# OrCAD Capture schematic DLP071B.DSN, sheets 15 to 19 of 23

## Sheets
15 PAGE09 - 2ND PMD POWER SUPPLIES: size A3
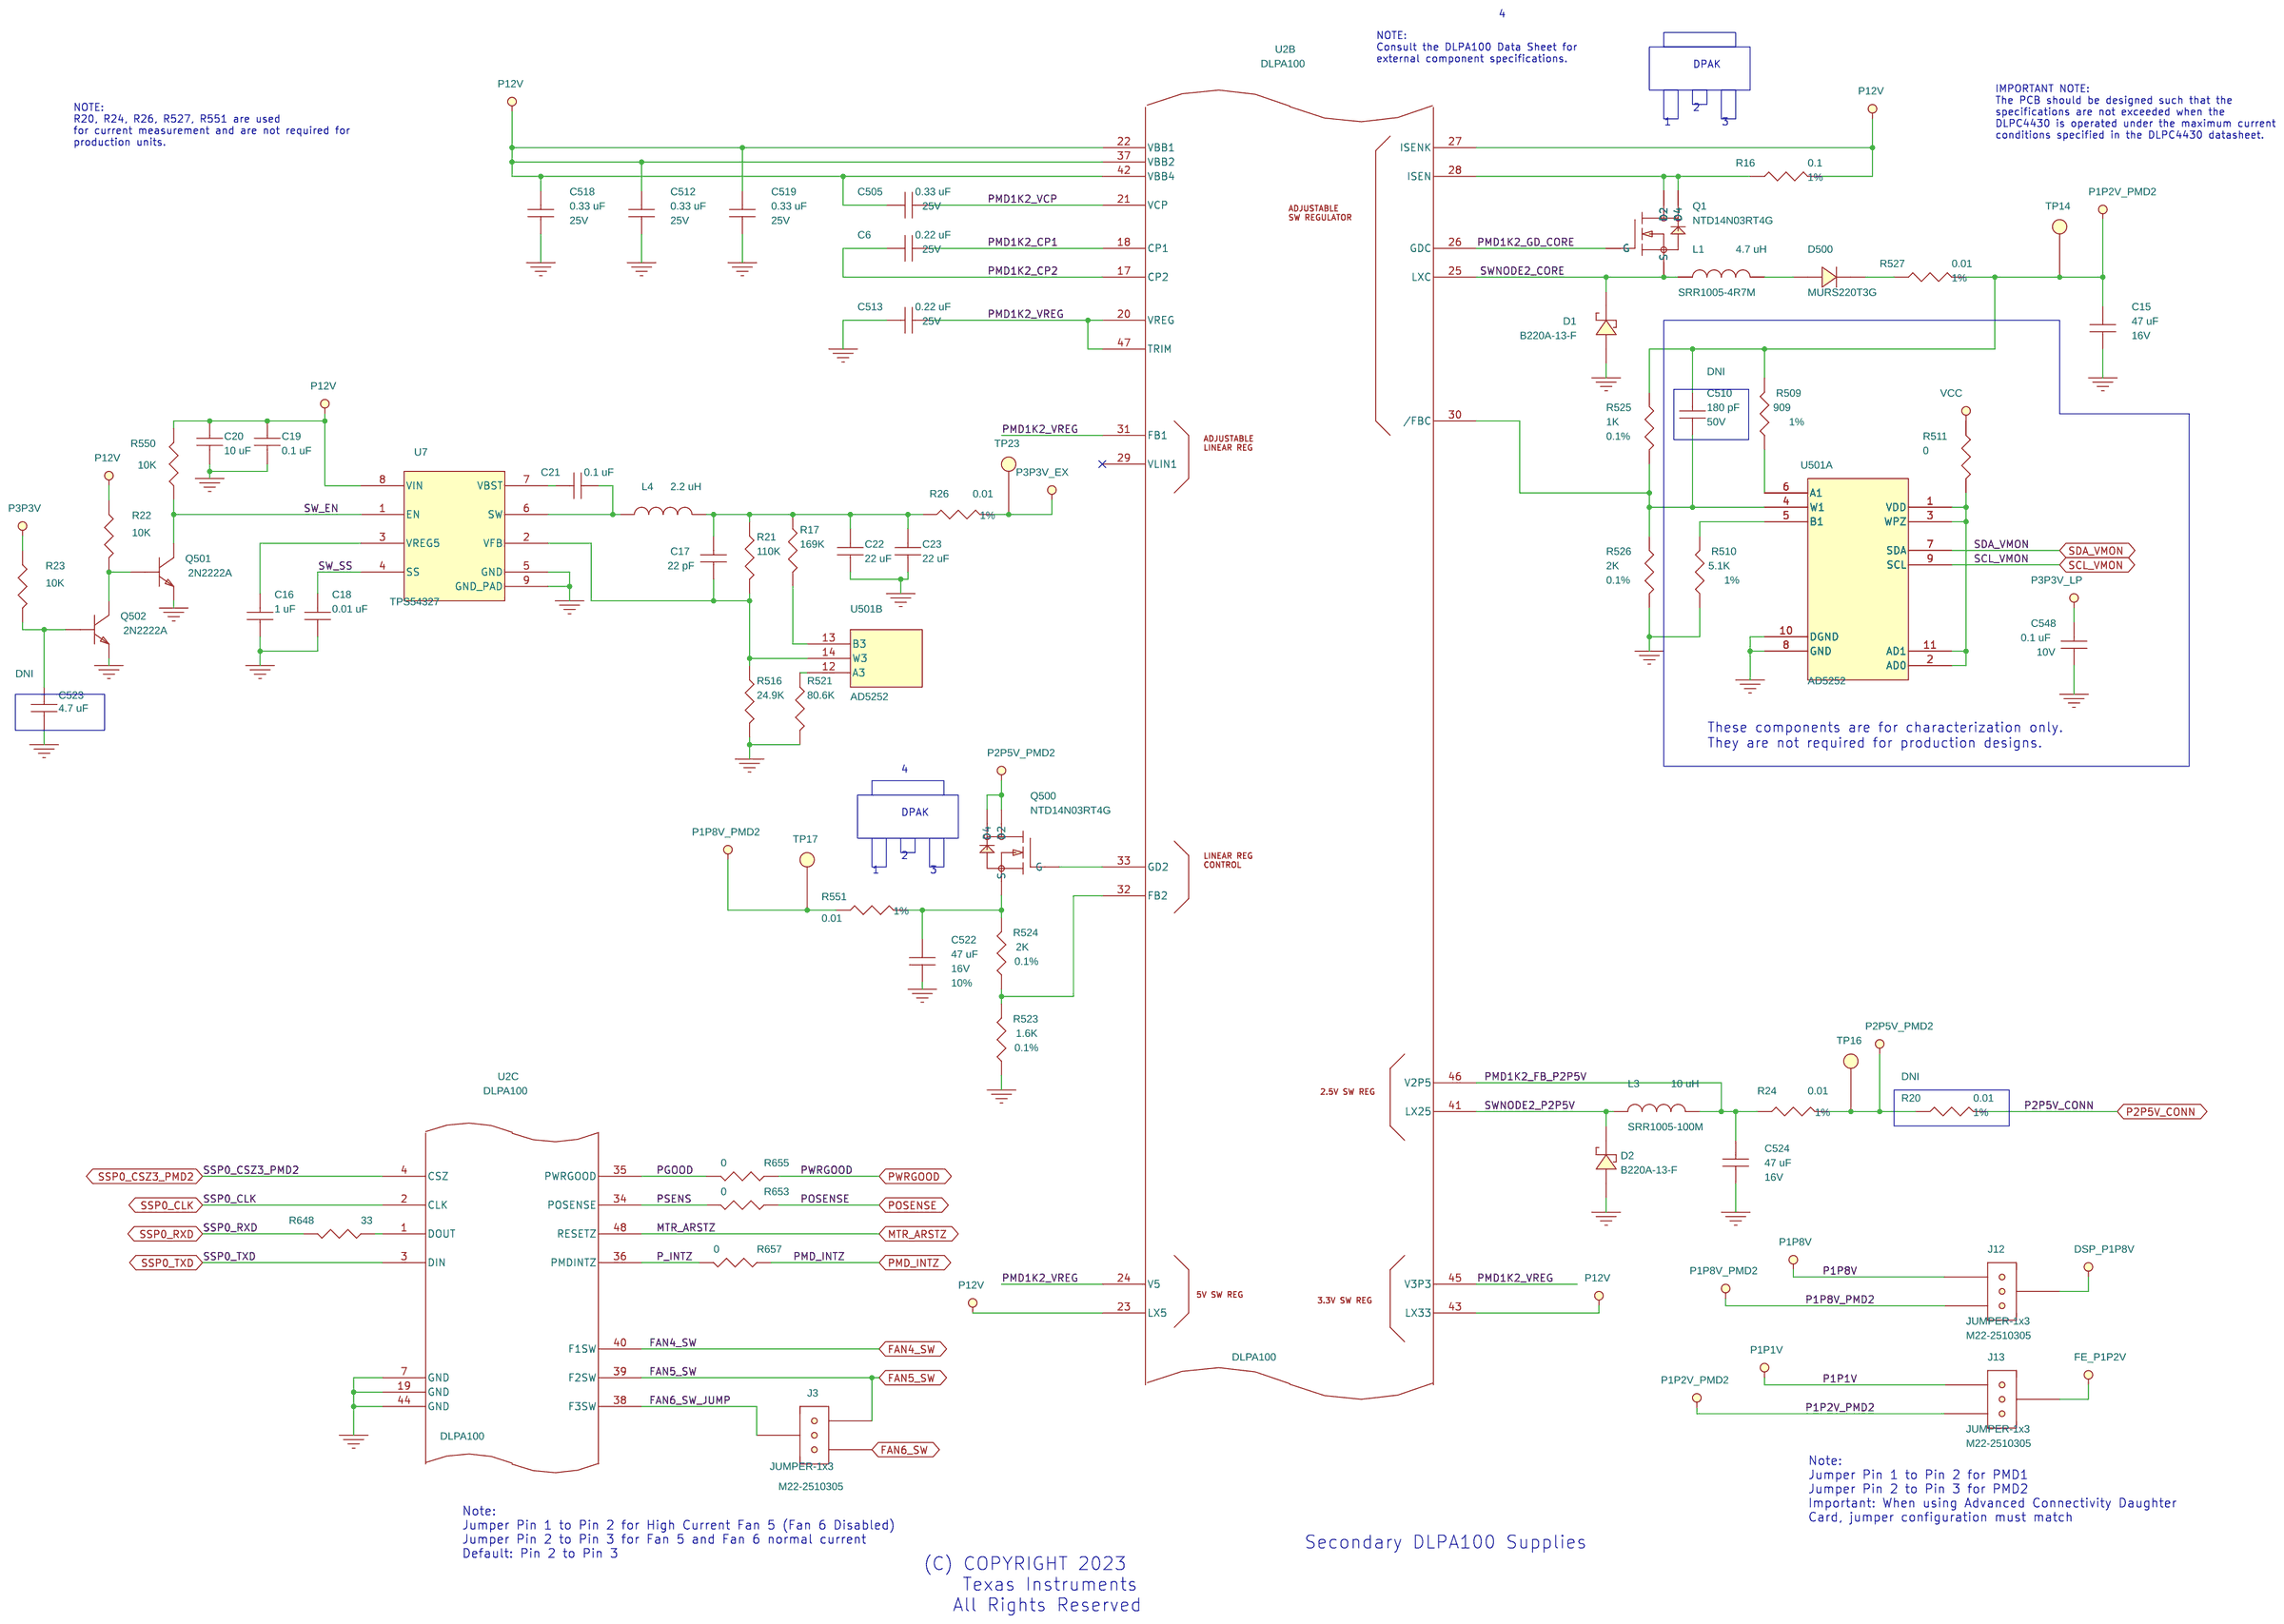
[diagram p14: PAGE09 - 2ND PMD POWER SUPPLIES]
16 PAGE08 - DLPA100 POWER SUPPLIES: size A3
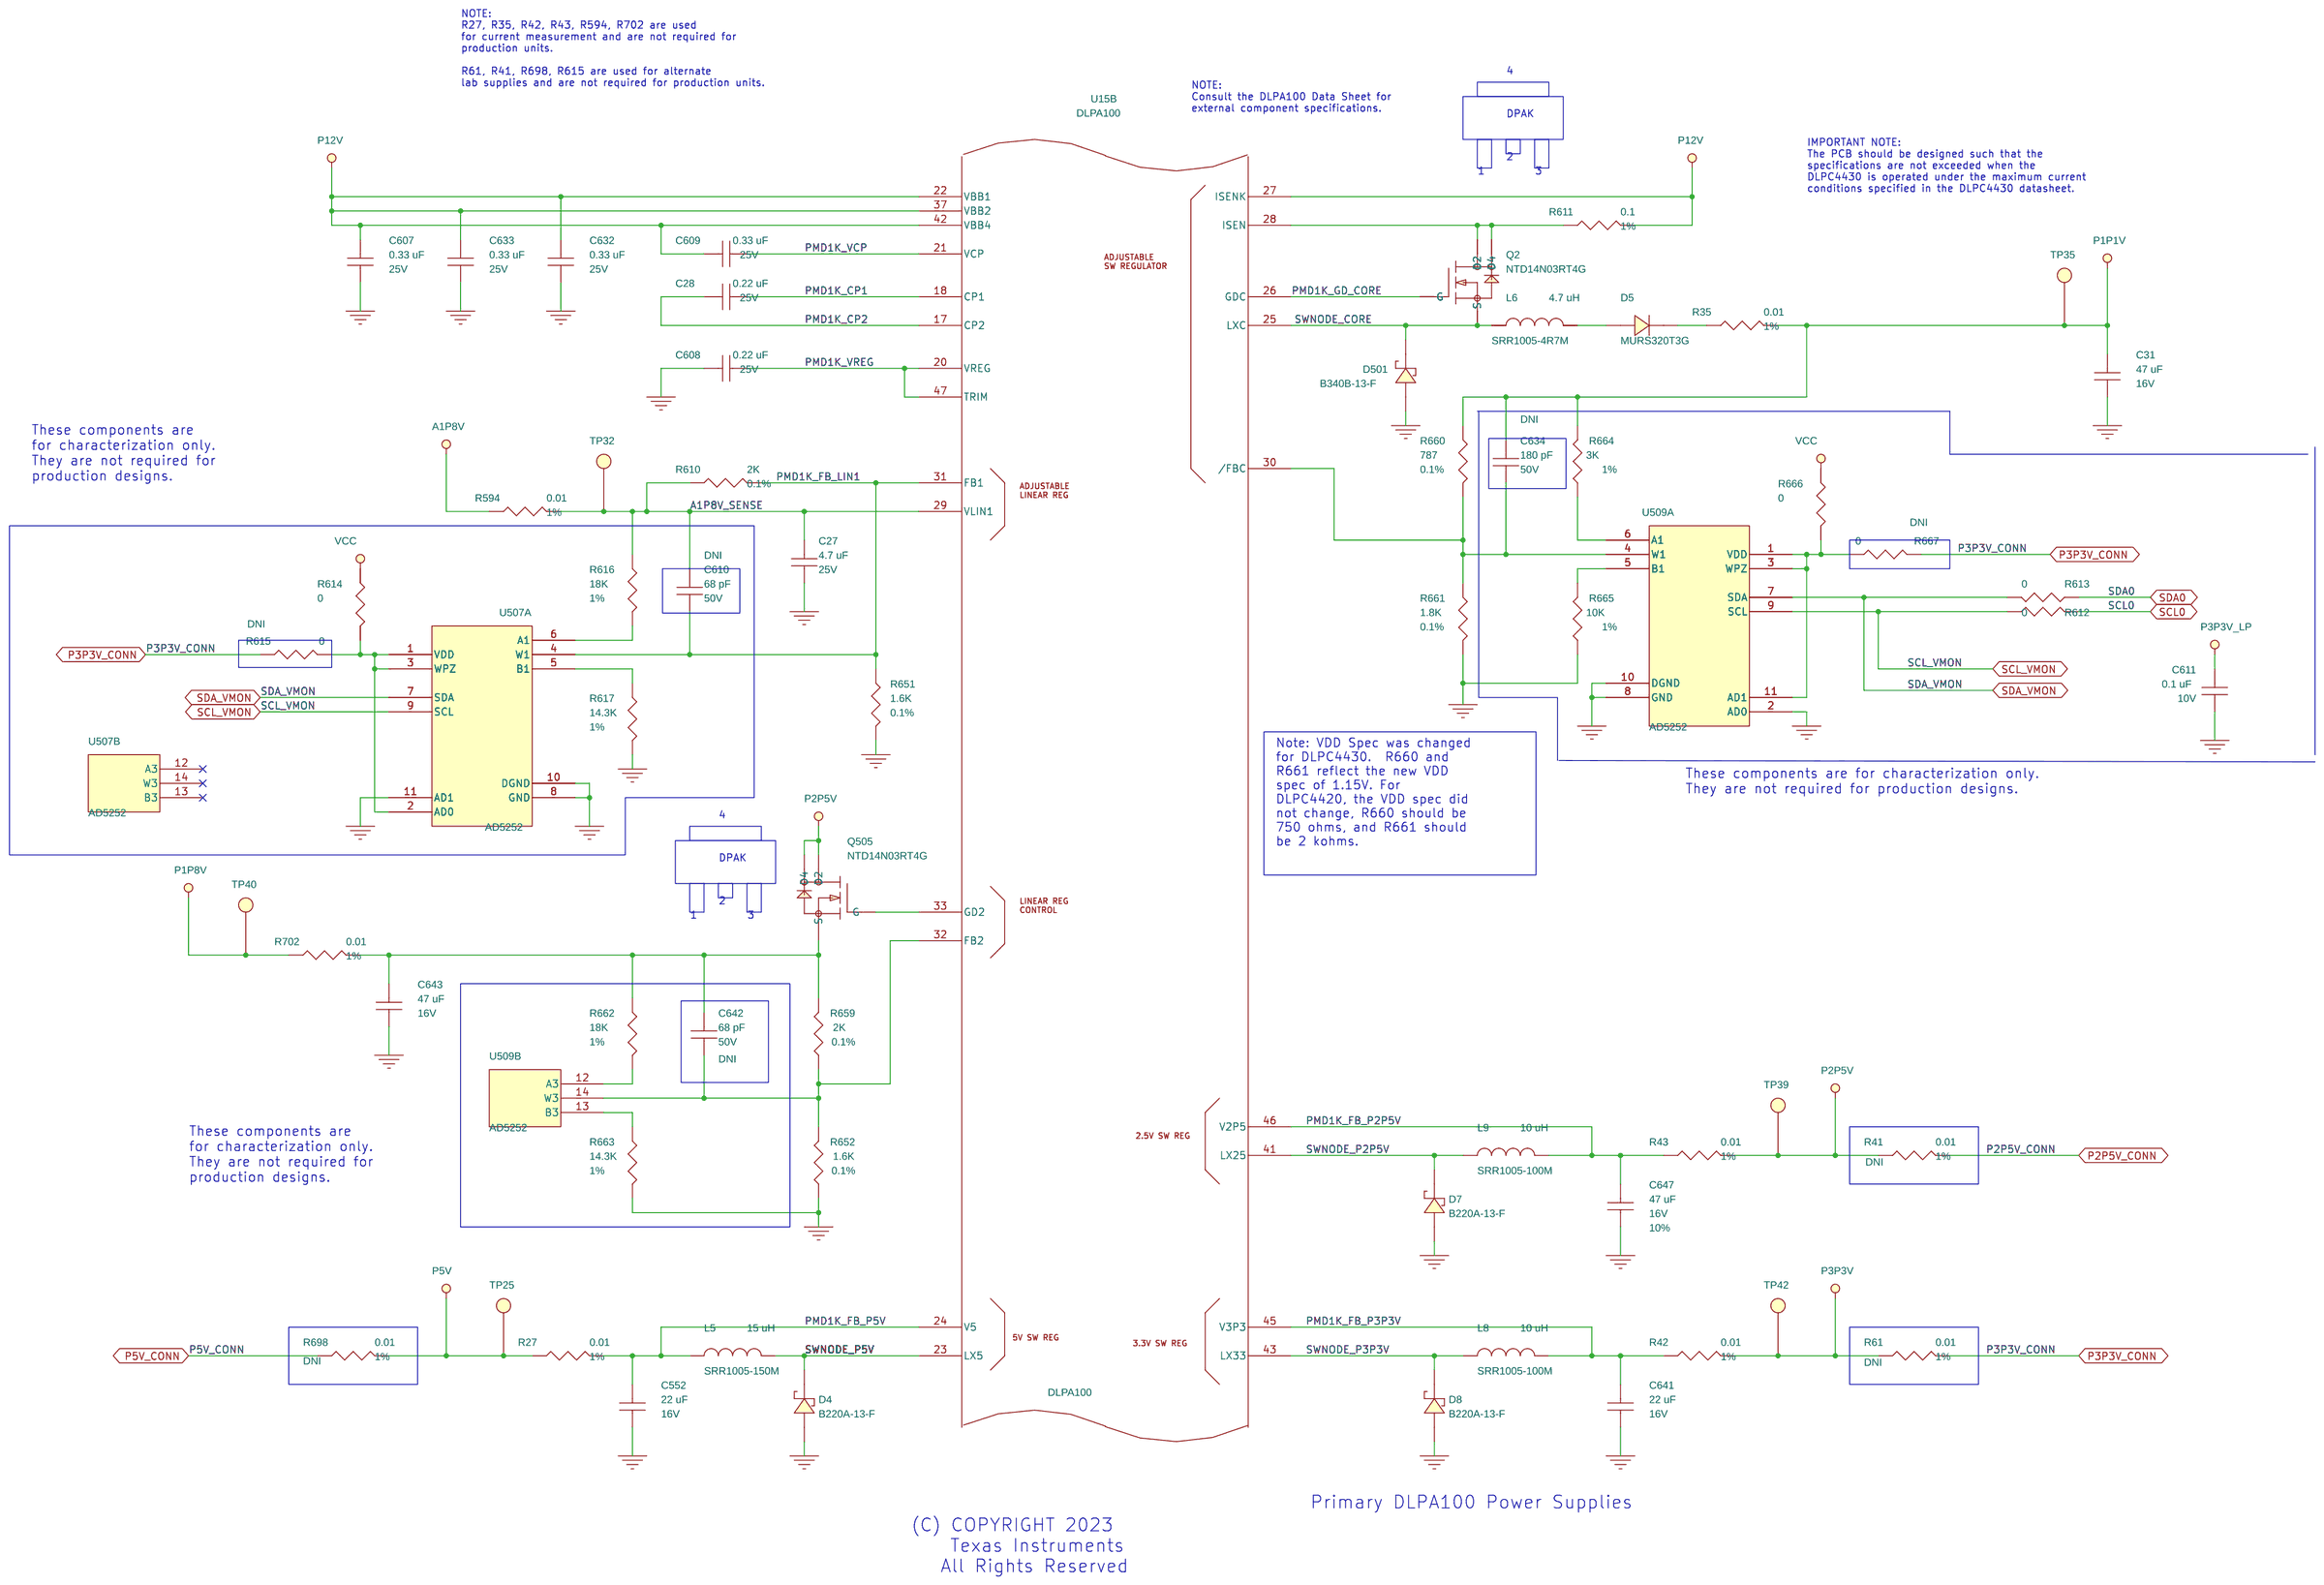
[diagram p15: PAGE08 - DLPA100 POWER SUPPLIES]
17 PAGE07 - INPUT PWR & DLPA100: size A3
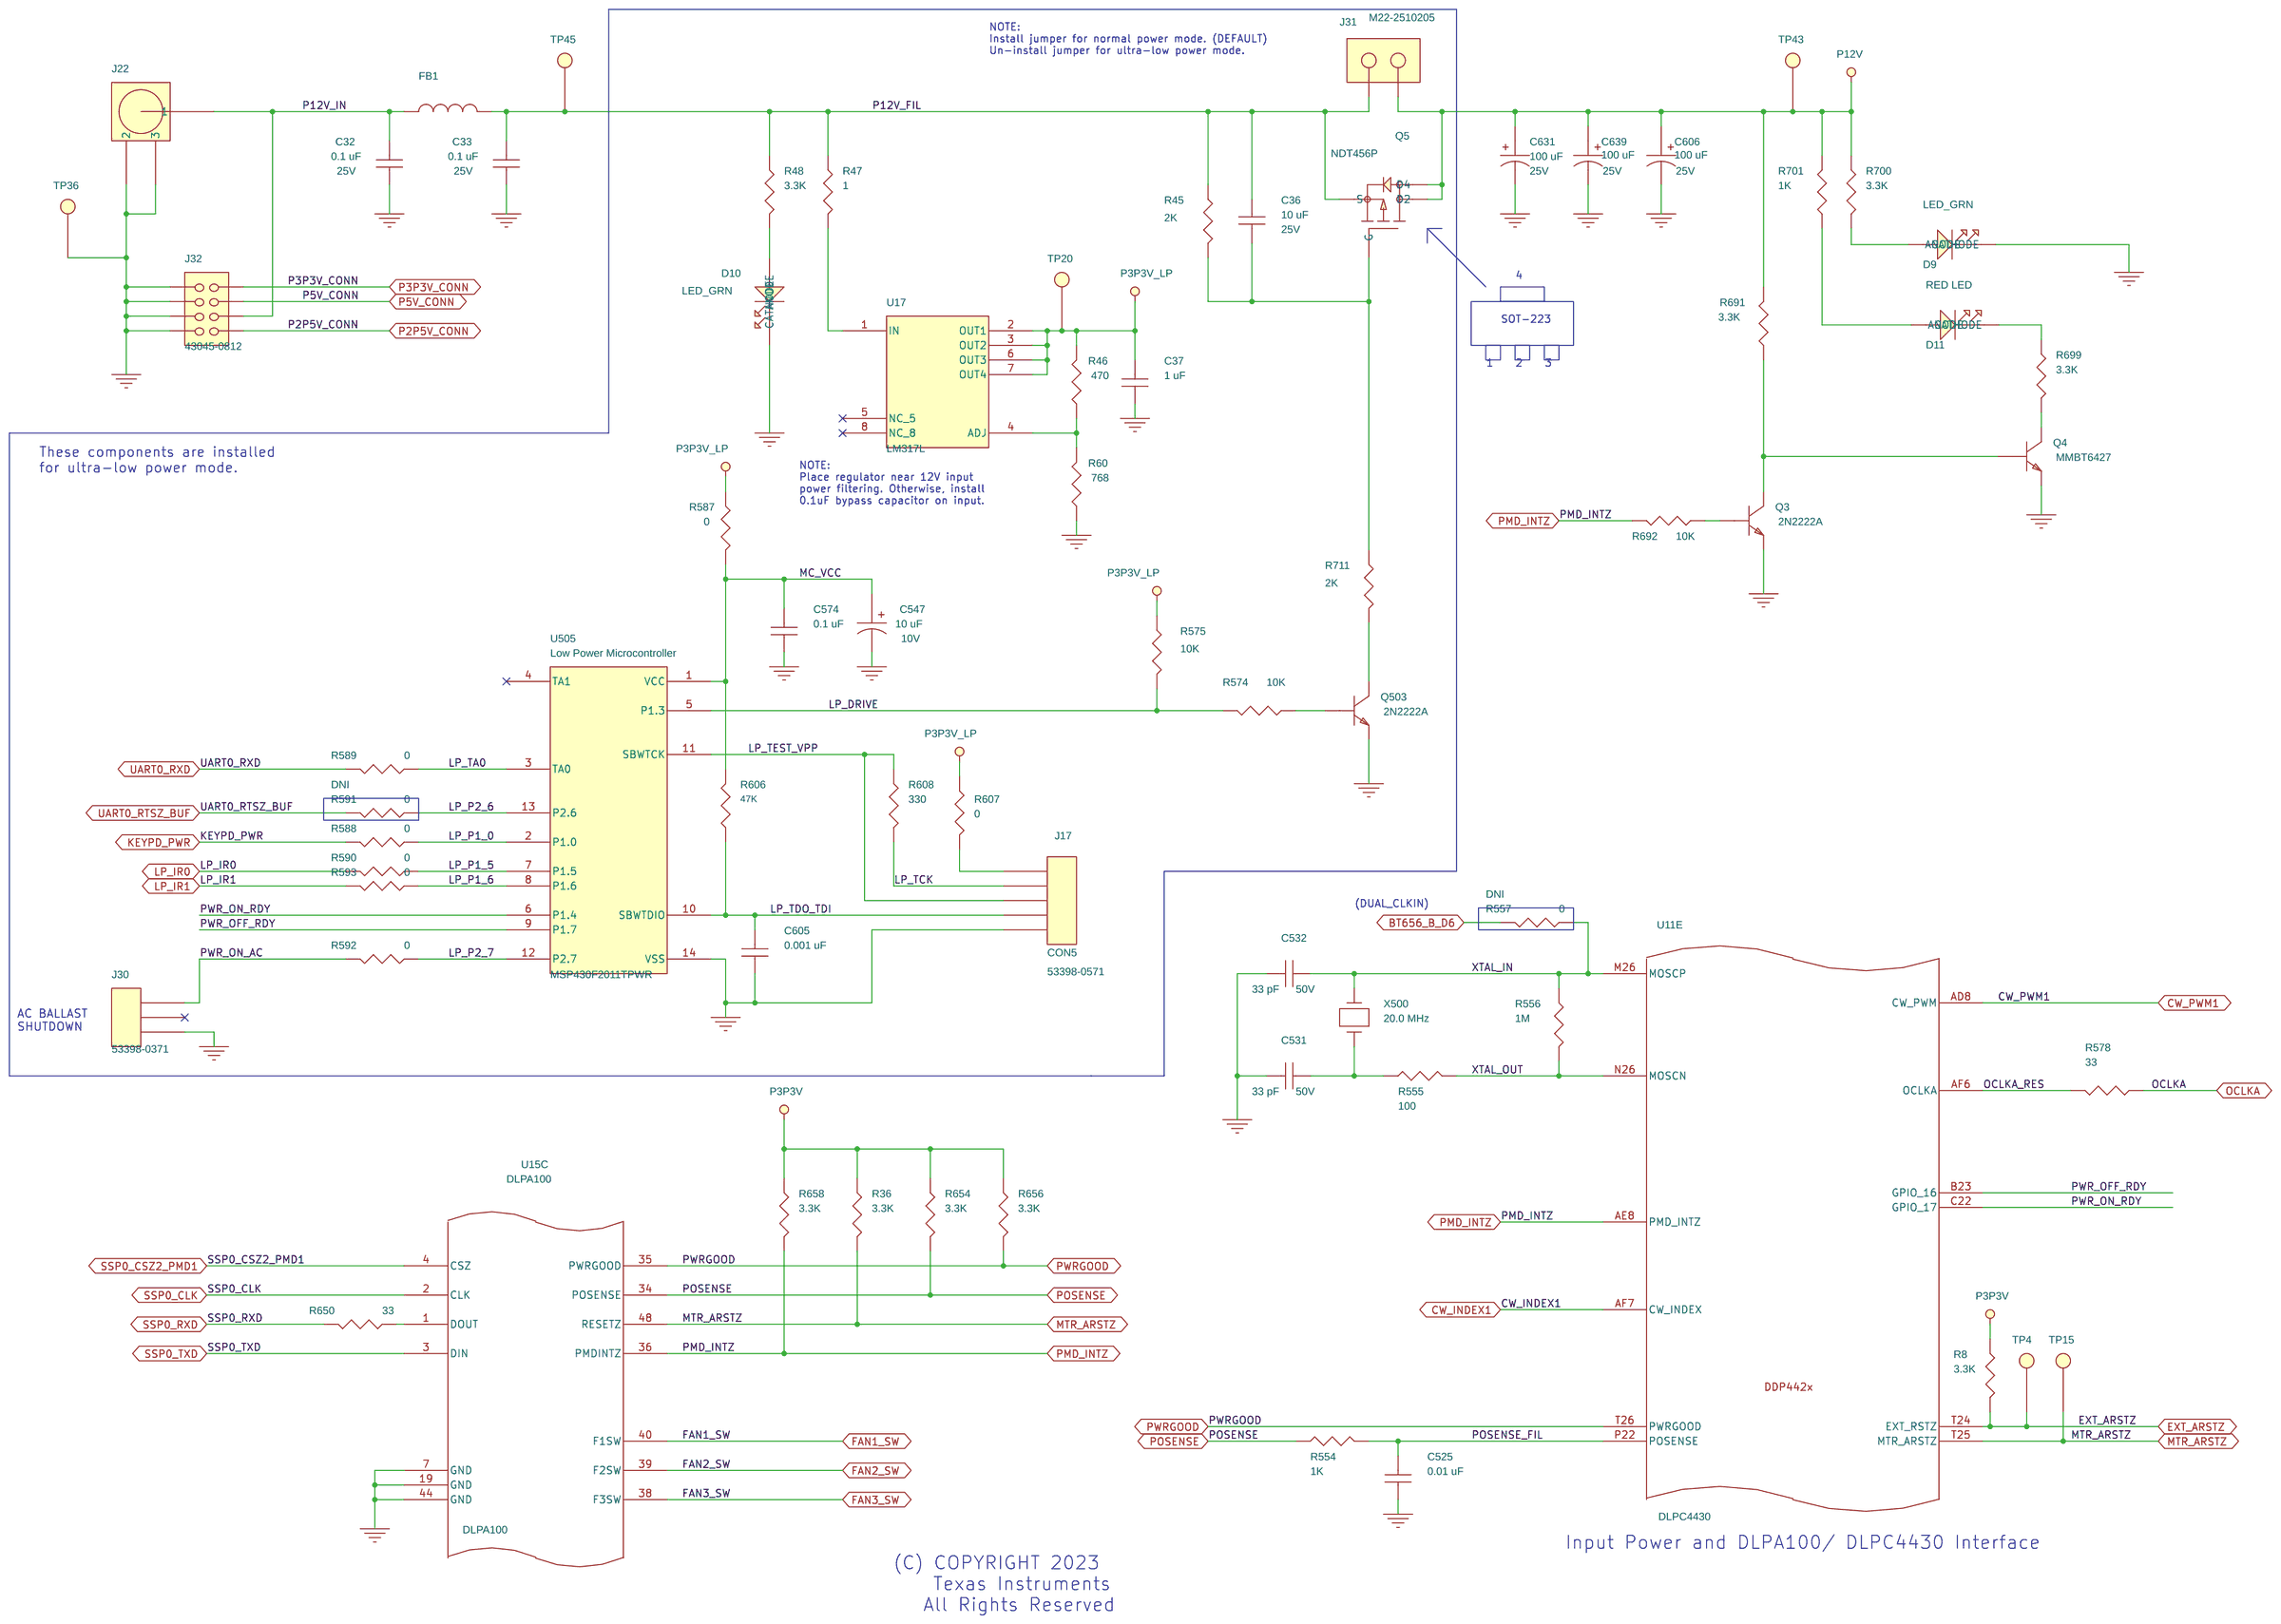
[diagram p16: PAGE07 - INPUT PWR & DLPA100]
18 PAGE06 - DMD INTERFACE: size A3
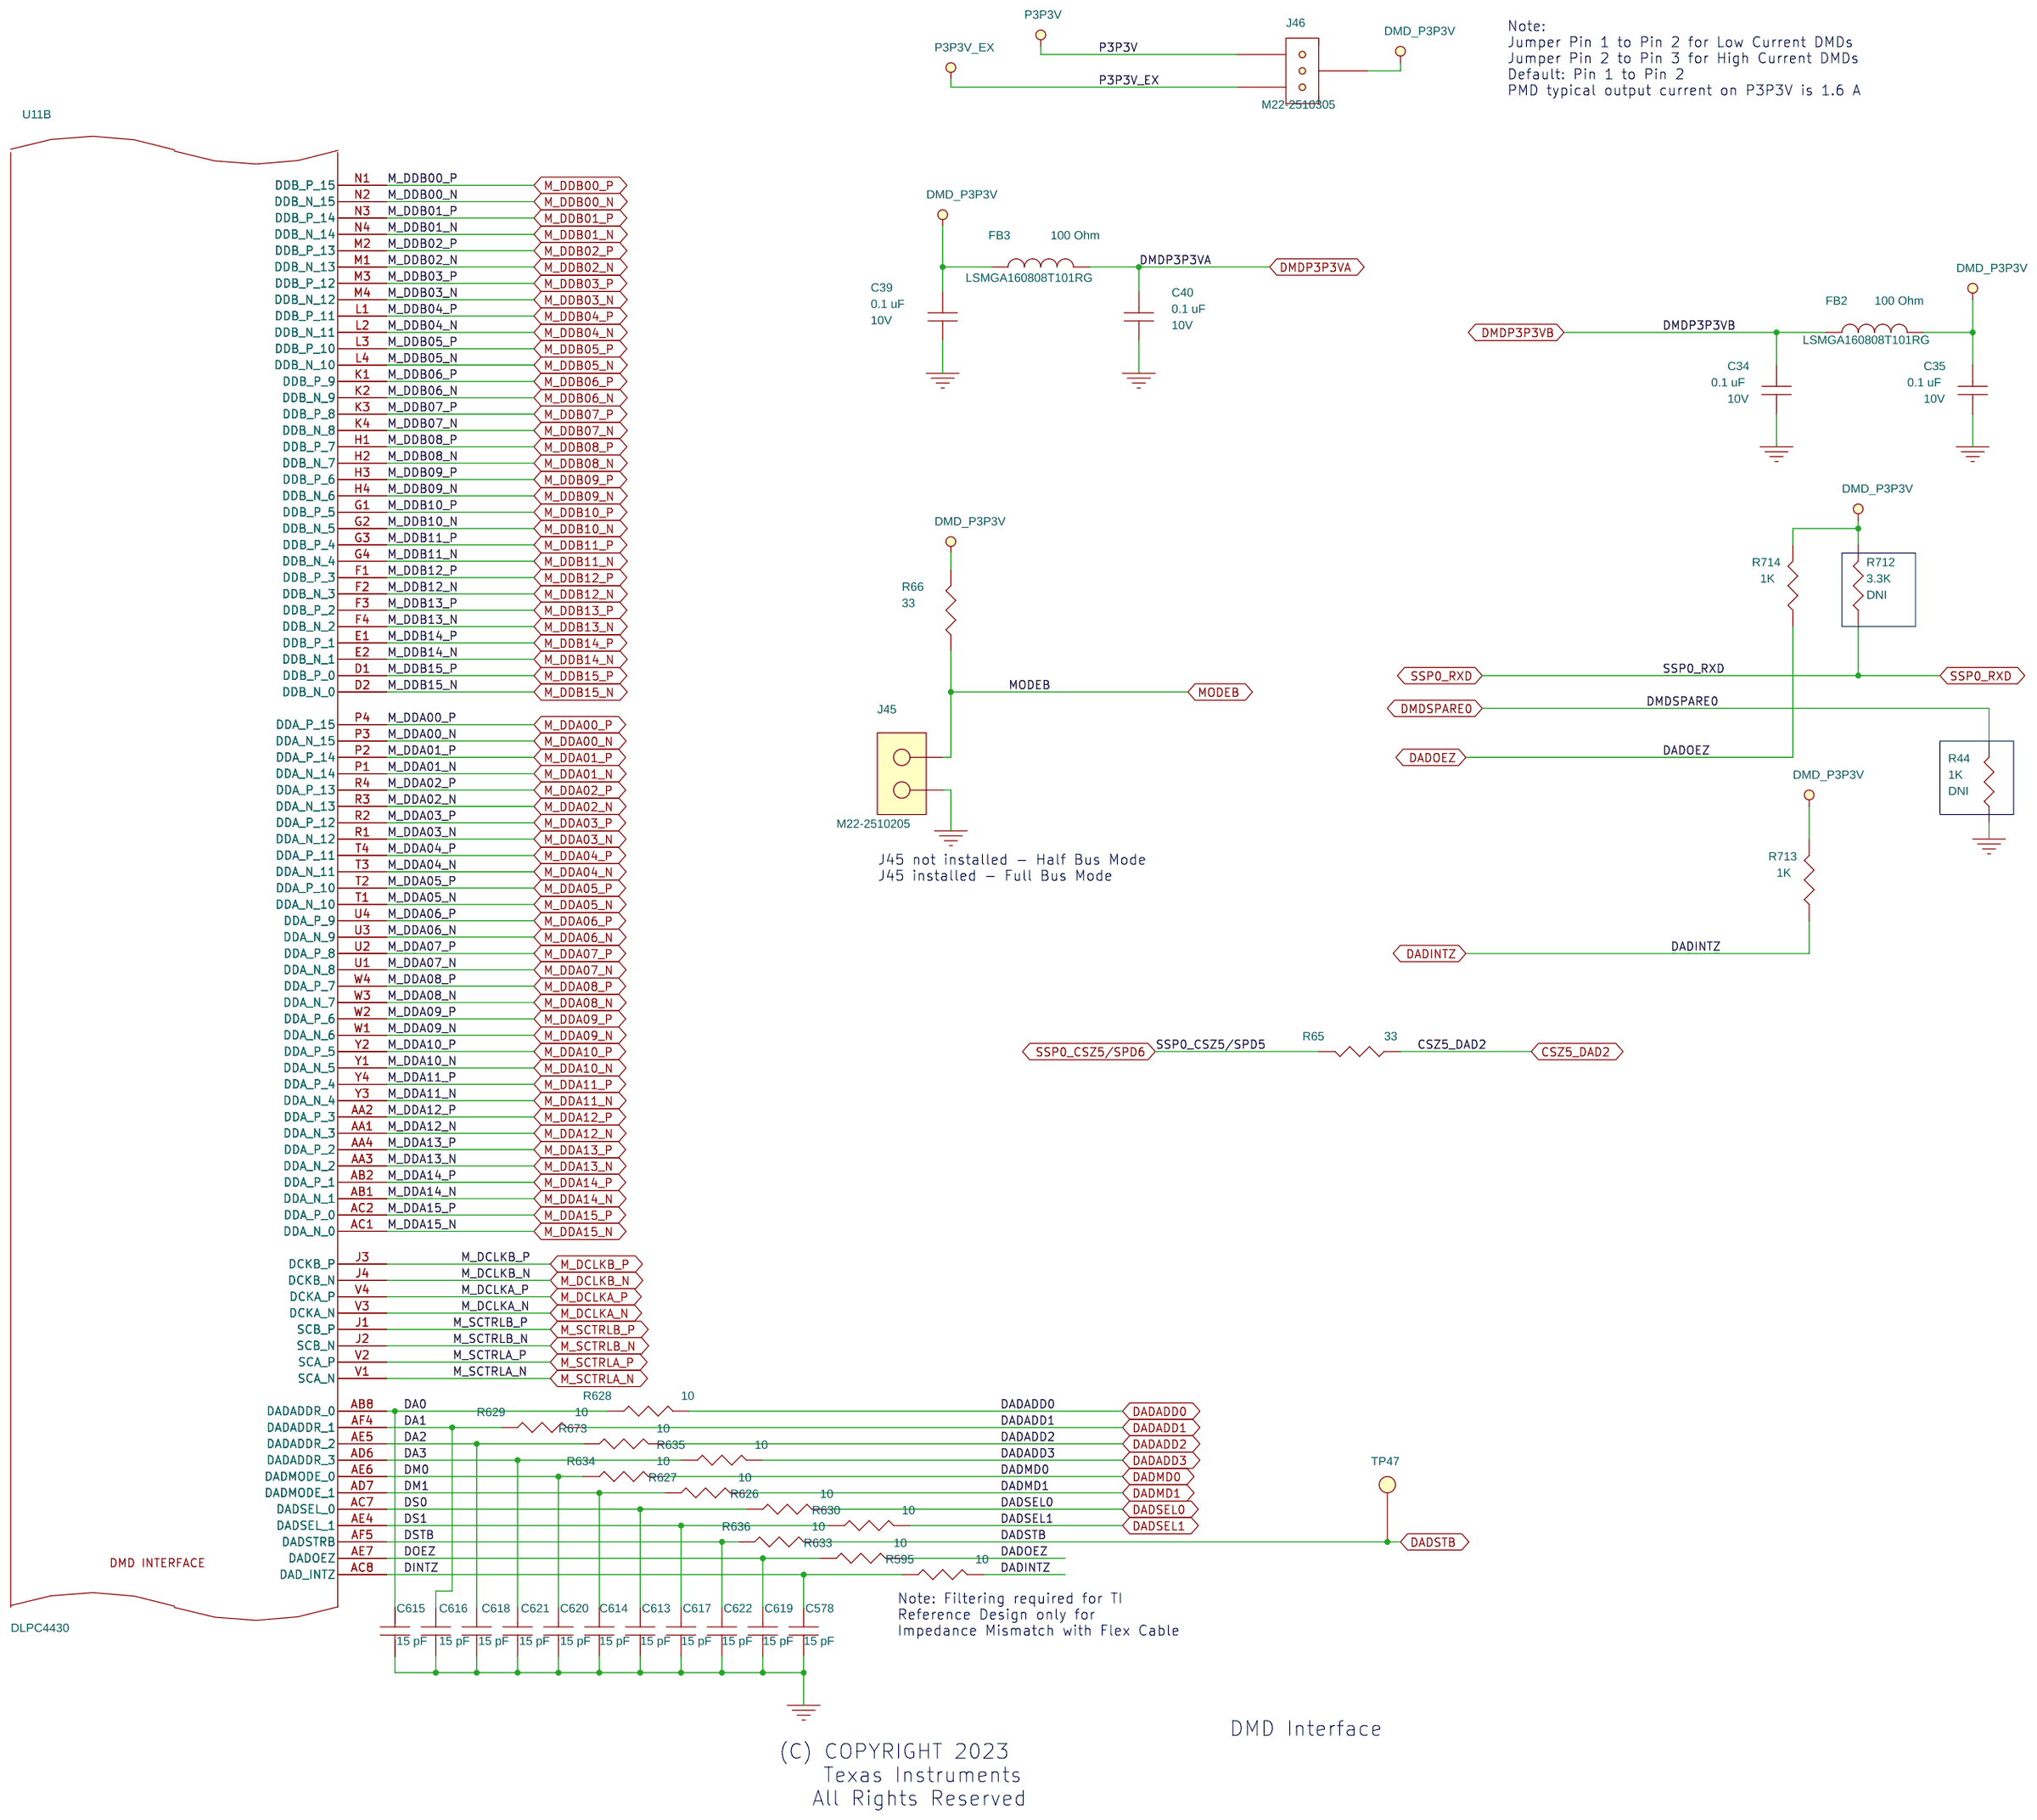
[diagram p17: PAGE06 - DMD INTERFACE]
19 PAGE05 - FRONT END INTERFACE: size A3
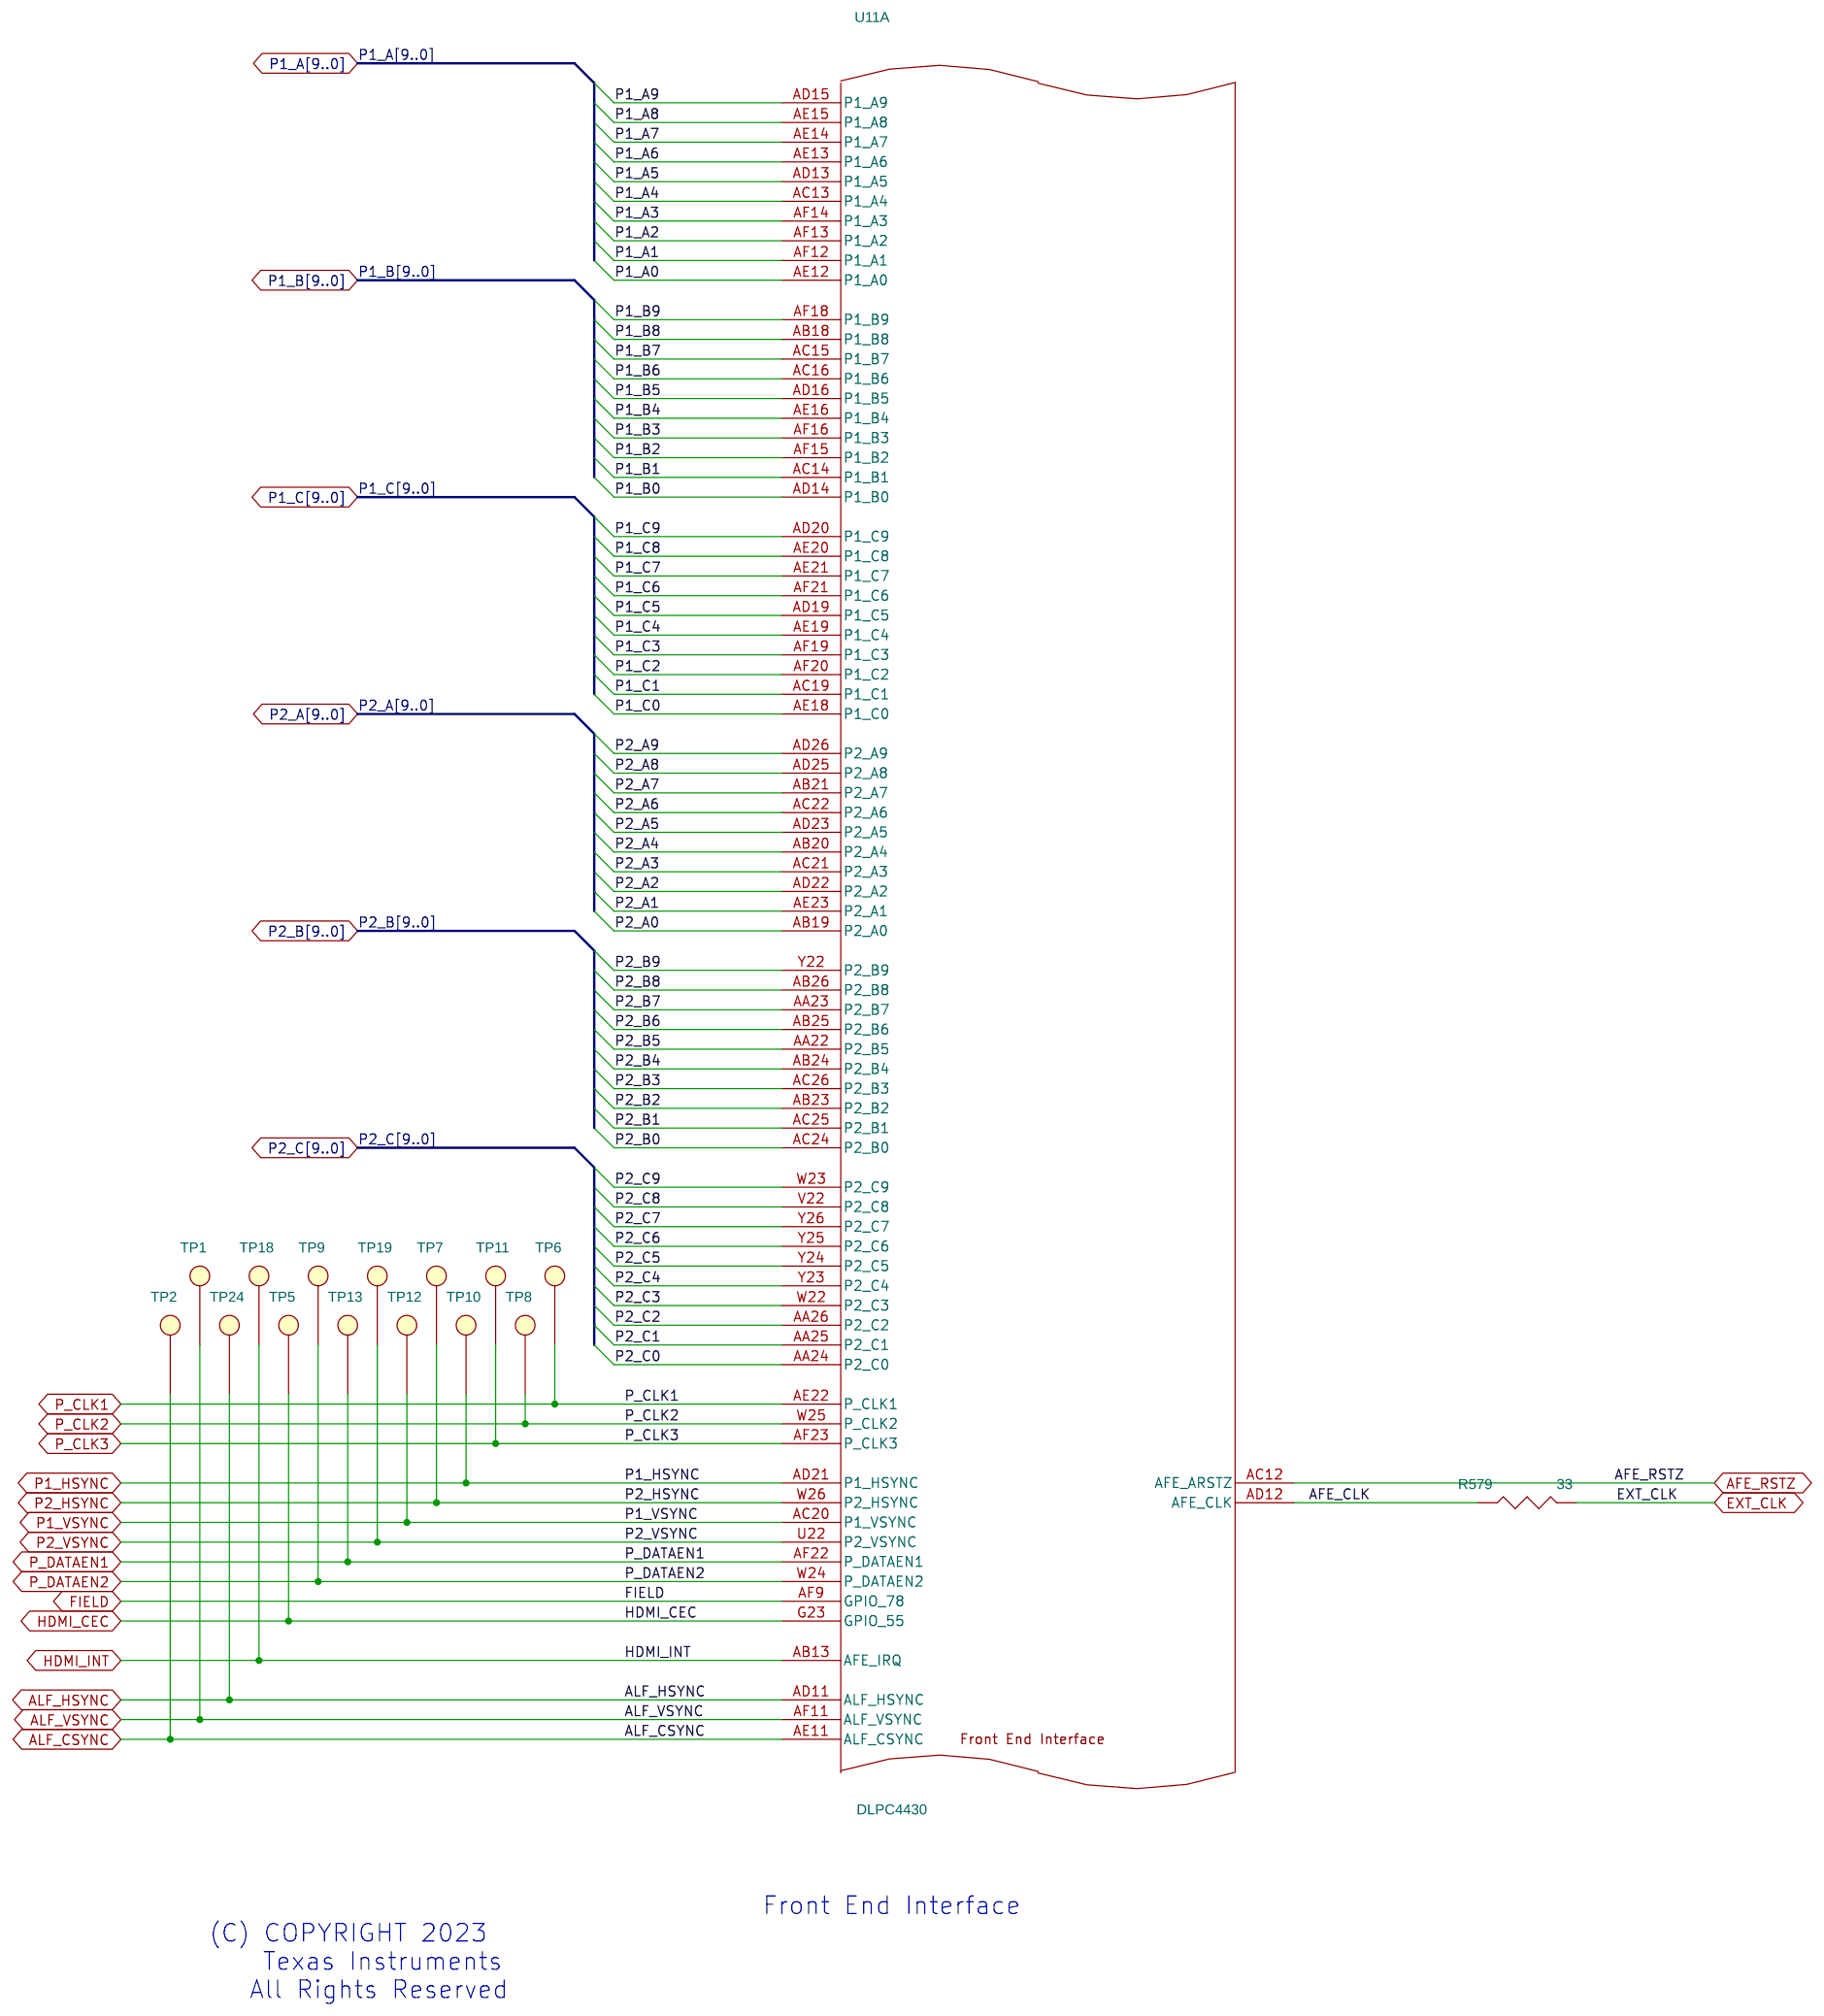
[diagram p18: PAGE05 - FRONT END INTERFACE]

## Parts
sheet PAGE05 - FRONT END INTERFACE
R579  33  [RES_0402]
TP1  Testpoint  [TP]
TP2  Testpoint  [TP]
TP5  Testpoint  [TP]
TP6  Testpoint  [TP]
TP7  Testpoint  [TP]
TP8  Testpoint  [TP]
TP9  Testpoint  [TP]
TP10  Testpoint  [TP]
TP11  Testpoint  [TP]
TP12  Testpoint  [TP]
TP13  Testpoint  [TP]
TP18  Testpoint  [TP]
TP19  Testpoint  [TP]
TP24  Testpoint  [TP]
sheet PAGE06 - DMD INTERFACE
C34  0.1 uF  [CAP_0402]
C35  0.1 uF  [CAP_0402]
C39  0.1 uF  [CAP_0402]
C40  0.1 uF  [CAP_0402]
C578  15 pF  [CAP_0402]
C613  15 pF  [CAP_0402]
C614  15 pF  [CAP_0402]
C615  15 pF  [CAP_0402]
C616  15 pF  [CAP_0402]
C617  15 pF  [CAP_0402]
C618  15 pF  [CAP_0402]
C619  15 pF  [CAP_0402]
C620  15 pF  [CAP_0402]
C621  15 pF  [CAP_0402]
C622  15 pF  [CAP_0402]
FB2  100 Ohm  [FLTR_0603]
FB3  100 Ohm  [FLTR_0603]
J45  HDR_2  [HDR2_2MM]
J46  JUMPER-1x3  [HDR1X3-TMM1030X-X-S_SAM]
R44  1K  [RES_0402]
R65  33  [RES_0402]
R66  33  [RES_0402]
R595  10  [RES_0402]
R626  10  [RES_0402]
R627  10  [RES_0402]
R628  10  [RES_0402]
R629  10  [RES_0402]
R630  10  [RES_0402]
R633  10  [RES_0402]
R634  10  [RES_0402]
R635  10  [RES_0402]
R636  10  [RES_0402]
R673  10  [RES_0402]
R712  3.3K  [RES_0402]
R713  1K  [RES_0402]
R714  1K  [RES_0402]
TP47  Testpoint  [TP]
sheet PAGE07 - INPUT PWR & DLPA100
C32  0.1 uF  [CAP_0603]
C33  0.1 uF  [CAP_0603]
C36  10 uF  [CAP_1210]
C37  1 uF  [CAP_0805]
C525  0.01 uF  [CAP_0603]
C531  33 pF  [CAP_0402]
C532  33 pF  [CAP_0402]
C547  10 uF  [CAP_0805]
C574  0.1 uF  [CAP_0402]
C605  0.001 uF  [CAP_0805]
C606  100 uF  [CAP-FK-V-CASEE_PAN]
C631  100 uF  [CAP-FK-V-CASEE_PAN]
C639  100 uF  [CAP-FK-V-CASEE_PAN]
D9  LED_GRN  [LED-0402-REV]
D10  LED_GRN  [LED-0402-REV]
D11  RED LED  [LED-0402-REV]
FB1  80 ohm  [IND_0805]
J17  CON5  [CONN5-53398-0590-a_MOLEX]
J22  POWER_12V_INPUT  [JACK3-DCPOWER_CUI_MOD]
J30  CON3  [CN3_53398_MOLEX]
J31  HDR_2  [HDR2_2MM]
J32  JUMPER_8A  [CONN8-43045-0813_MOLEX]
Q3  2N2222A  [SOT23AVXD]
Q4  MMBT6427  [SOT23AVXD]
Q5  NDT456P  [SOT223]
Q503  2N2222A  [SOT23AVXD]
R8  3.3K  [RES_0402]
R36  3.3K  [RES_0402]
R45  2K  [RES_0402]
R46  470  [RES_0402]
R47  1  [RES_0603]
R48  3.3K  [RES_0402]
R60  768  [RES_0402]
R554  1K  [RES_0402]
R555  100  [RES_0402]
R556  1M  [RES_0402]
R557  0  [RES_0402]
R574  10K  [RES_0402]
R575  10K  [RES_0402]
R578  33  [RES_0402]
R587  0  [RES_0402]
R588  0  [RES_0402]
R589  0  [RES_0402]
R590  0  [RES_0402]
R591  0  [RES_0402]
R592  0  [RES_0402]
R593  0  [RES_0402]
R606  47K  [RES_0402]
R607  0  [RES_0402]
R608  330  [RES_0402]
R650  33  [RES_0402]
R654  3.3K  [RES_0402]
R656  3.3K  [RES_0402]
R658  3.3K  [RES_0402]
R691  3.3K  [RES_0402]
R692  10K  [RES_0402]
R699  3.3K  [RES_0402]
R700  3.3K  [RES_0402]
R701  1K  [RES_0402]
R711  2K  [RES_0402]
TP4  Testpoint  [TP]
TP15  Testpoint  [TP]
TP20  Testpoint  [TP]
TP36  Testpoint  [TP]
TP43  Testpoint  [TP]
TP45  Testpoint  [TP]
U17  LM317L  [SOIC8-D_TI]
U505  Low Power Microcontroller  [SOIC14-PW_TI]
X500  20.0 MHz  [SMD_49]
sheet PAGE08 - DLPA100 POWER SUPPLIES
C27  4.7 uF  [CAP_0805]
C28  0.22 uF  [CAP_0805]
C31  47 uF  [CAP_1210]
C552  22 uF  [CAP_1210]
C607  0.33 uF  [CAP_0805]
C608  0.22 uF  [CAP_0805]
C609  0.33 uF  [CAP_0805]
C610  68 pF  [CAP_0603]
C611  0.1 uF  [CAP_0402]
C632  0.33 uF  [CAP_0805]
C633  0.33 uF  [CAP_0805]
C634  180 pF  [CAP_0603]
C641  22 uF  [CAP_1210]
C642  68 pF  [CAP_0603]
C643  47 uF  [CAP_1210]
C647  47 uF  [CAP_1210]
D4  B220A  [DIO-SMA]
D5  MUR320T3G  [SMC_ST]
D7  B220A  [DIO-SMA]
D8  B220A  [DIO-SMA]
D501  B340B  [DIO-SMB]
L5  15 uH  [IND_SRR1005]
L6  4.7 uH  [IND_SRR1005]
L8  10 uH  [IND_SRR1005]
L9  10 uH  [IND_SRR1005]
Q2  NTD14N03RT4G  [SM_TO_252_DPAK]
Q505  NTD14N03RT4G  [SM_TO_252_DPAK]
R27  0.01  [RES_0805]
R35  0.01  [RES_0805]
R41  0.01  [RES_0805]
R42  0.01  [RES_0805]
R43  0.01  [RES_0805]
R61  0.01  [RES_0805]
R594  0.01  [RES_0805]
R610  2K  [RES_0402]
R611  0.1  [RES_0805]
R612  0  [RES_0402]
R613  0  [RES_0402]
R614  0  [RES_0402]
R615  0  [RES_0402]
R616  18K  [RES_0402]
R617  14.3K  [RES_0402]
R651  1.6K  [RES_0402]
R652  1.6K  [RES_0402]
R659  2K  [RES_0402]
R660  787  [RES_0402]
R661  1.8K  [RES_0402]
R662  18K  [RES_0402]
R663  14.3K  [RES_0402]
R664  3K  [RES_0402]
R665  10K  [RES_0402]
R666  0  [RES_0402]
R667  0  [RES_0402]
R698  0.01  [RES_0805]
R702  0.01  [RES_0805]
TP25  Testpoint  [TP]
TP32  Testpoint  [TP]
TP35  Testpoint  [TP]
TP39  Testpoint  [TP]
TP40  Testpoint  [TP]
TP42  Testpoint  [TP]
U15  DLPA100  [QF48_PPAD]  (sections A,B,C)
U507  AD5252  [TSSOP_14]  (sections A,B)
U509  AD5252  [TSSOP_14]  (sections A,B)
sheet PAGE09 - 2ND PMD POWER SUPPLIES
C6  0.22 uF  [CAP_0805]
C15  47 uF  [CAP_1210]
C16  1 uF  [CAP_0805]
C17  22 pF  [CAP_0402]
C18  0.01 uF  [CAP_0603]
C19  0.1 uF  [CAP_0603]
C20  10 uF  [CAP_1210]
C21  0.1 uF  [CAP_0603]
C22  22 uF  [CAP_1210]
C23  22 uF  [CAP_1210]
C505  0.33 uF  [CAP_0805]
C510  180 pF  [CAP_0603]
C512  0.33 uF  [CAP_0805]
C513  0.22 uF  [CAP_0805]
C518  0.33 uF  [CAP_0805]
C519  0.33 uF  [CAP_0805]
C522  47 uF  [CAP_1210]
C523  4.7 uF  [CAP_0805]
C524  47 uF  [CAP_1210]
C548  0.1 uF  [CAP_0402]
D1  B220A  [DIO-SMA]
D2  B220A  [DIO-SMA]
D500  MURS220T3G  [DIO-SMB]
J3  JUMPER-1x3  [HDR1X3-TMM1030X-X-S_SAM]
J12  JUMPER-1x3  [HDR1X3-TMM1030X-X-S_SAM]
J13  JUMPER-1x3  [HDR1X3-TMM1030X-X-S_SAM]
L1  4.7 uH  [IND_SRR1005]
L3  10 uH  [IND_SRR1005]
L4  2.2 uH  [IND2-7447789002-7332_WURTH]
Q1  NTD14N03RT4G  [SM_TO_252_DPAK]
Q500  NTD14N03RT4G  [SM_TO_252_DPAK]
Q501  2N2222A  [SOT23AVXD]
Q502  2N2222A  [SOT23AVXD]
R16  0.1  [RES_0805]
R17  169K  [RES_0402]
R20  0.01  [RES_0805]
R21  110K  [RES_0402]
R22  10K  [RES_0402]
R23  10K  [RES_0402]
R24  0.01  [RES_0805]
R26  0.01  [RES_0805]
R509  909  [RES_0402]
R510  5.1K  [RES_0402]
R511  0  [RES_0402]
R516  24.9K  [RES_0402]
R521  80.6K  [RES_0402]
R523  1.6K  [RES_0402]
R524  2K  [RES_0402]
R525  1K  [RES_0402]
R526  2K  [RES_0402]
R527  0.01  [RES_0805]
R550  10K  [RES_0402]
R551  0.01  [RES_0805]
R648  33  [RES_0402]
R653  0  [RES_0402]
R655  0  [RES_0402]
R657  0  [RES_0402]
TP14  Testpoint  [TP]
TP16  Testpoint  [TP]
TP17  Testpoint  [TP]
TP23  Testpoint  [TP]
U2  DLPA100  [QF48_PPAD]  (sections A,B,C)
U7  TPS54327  [SOIC8-DDA_TI]
U501  AD5252  [TSSOP_14]  (sections A,B)
sheet PAGE15 - RS-232, SSP, USB
U11  DLPC4430  [BGA552-DDP4422_TI_MOD]  (sections A,B,C,D,E,F,G,H,I,J)

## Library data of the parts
R65 R66 R578 R579 R648 R650 = R: Resistor; ICA_MFR_NAME: PANASONIC; ICA_PARTNUM: $$1785048$$ERJ-3GSYJ102; MFG: PANASONIC; Part Number: ERJ-2GEJ330X; RATING: 1/10W; SOURCE: DIGI P33JCT-ND; TOLERANCE: 5%
TP1 TP2 TP4-TP20 TP23-TP25 TP32 TP35 TP36 TP39 TP40 TP42 TP43 TP45 TP47 = Testpoint: Test point
C34 C35 C39 C40 C548 C574 C611 = CAP_NP: Capacitor; MFG: KEMET; Part Number: C0402C104K8RACTU; RATING: 10V; SOURCE: DIGI 399-3520-1-ND; TOLERANCE: 10%; Type: X7R
C578 C613-C622 = CAP_NP: Capacitor; MFG: AVX; Part Number: 0402YA150JAT2A; RATING: 16V; SOURCE: DIGI 0402YA150JAT2A-ND; TOLERANCE: 5%; Type: NP0
FB2 FB3 = INDUCTOR: Ferrite; ICA_MFR_NAME: STEWARD; ICA_PARTNUM: $$731362$$MI0603J680R-10; MFG: Taiyo Yuden; Part Number: LSMGA160808T101RG; RATING: 2.5A, 100MHz; SOURCE: DIGI 587-LSMGA160808T101RGTR-ND
J45 = HDR_2: Jumper, 1x2; MFG: HARWIN; Part Number: M22-2510205; SOURCE: DIGI 952-1311-ND
J3 J12 J13 J46 = JUMPER-1x3: Jumper, 1x3; MFG: HARWIN; Part Number: M22-2510305; SOURCE: DIGI 952-1312-ND
R44 = R: Resistor; DNI: DNI; ICA_MFR_NAME: PANASONIC; ICA_PARTNUM: $$1785048$$ERJ-3GSYJ102; MFG: PANASONIC; Part Number: ERJ-2GEJ102X; RATING: 1/10W; SOURCE: DIGI P1.0KJCT-ND; TOLERANCE: 5%
R595 R626-R630 R633-R636 R673 = R: Resistor; MFG: YAGEO; Part Number: RC0402FR-0710RL; RATING: 1/16W; SOURCE: DIGI 311-10.0LRTR-ND; TOLERANCE: 1%
R712 = R: Resistor; DNI: DNI; ICA_MFR_NAME: PANASONIC; ICA_PARTNUM: $$1785048$$ERJ-3GSYJ102; MFG: PANASONIC; Part Number: ERJ-2GEJ332X; RATING: 1/10W; SOURCE: DIGI P3.3KJCT-ND; TOLERANCE: 5%
R554 R701 R713 R714 = R: Resistor; ICA_MFR_NAME: PANASONIC; ICA_PARTNUM: $$1785048$$ERJ-3GSYJ102; MFG: PANASONIC; Part Number: ERJ-2GEJ102X; RATING: 1/10W; SOURCE: DIGI P1.0KJCT-ND; TOLERANCE: 5%
C19 C21 C32 C33 = CAP_NP: Capacitor; MFG: YAGEO; Part Number: CC0603KRX7R8BB104; RATING: 25V; SOURCE: DIGI PCC2277CT-ND; TOLERANCE: 10%; Type: X7R
C20 C36 = CAP_NP: Capacitor; MFG: TDK; Part Number: C3225X7R1E106M; RATING: 25V; SOURCE: DIGI 445-1434-2-ND; TOLERANCE: 20%; Type: X7R
C16 C37 = CAP_NP: Capacitor; MFG: KEMET; Part Number: C0805C105K4RACTU; RATING: 16V; SOURCE: DIGI 399-1284-2-ND; TOLERANCE: 10%; Type: X7R
C18 C525 = CAP_NP: Capacitor; MFG: YAGEO; Part Number: CC0603KRX7R8BB103; RATING: 25V; TOLERANCE: 10%; Type: X7R
C531 C532 = CAP_NP: Capacitor; MFG: Kyocera AVX; Part Number: KGM05ACG1H330FH; RATING: 50V; SOURCE: DIGI 478-KGM05ACG1H330FHTR-ND; TOLERANCE: 1%; Type: NP0
C547 = CAP_POL: Capacitor; MFG: MURATA; Part Number: GRM21BR71A106KE51L; RATING: 10V; SOURCE: DIGI 490-3905-1-ND; TOLERANCE: 10%; Type: X7R
C605 = CAP_NP: Capacitor; MFG: AVX; Part Number: 08055C102KAT2A; RATING: 50V; SOURCE: DIGI 478-1371-1-ND; TOLERANCE: 10%; Type: X7R
C606 C631 C639 = CAP_POL: Capacitor; MFG: PANASONIC; Part Number: EEE-FK1E101P; RATING: 25V; SOURCE: DIGI PCE3796CT-ND; TOLERANCE: 20%
D9 D10 = LED_0: LED GREEN CLEAR 0402 SMD; Digikey Part Number: 67-1881-1-ND; MFG: LUMEX OPTO; Manuf Part Number: SML-LX0402SUGC-TR; Manufacturer: LUMEX OPTO; Manufacturer Part Number: SML-LX0402SUGC-TR; Part Number: SML-LX0402SUGC-TR
D11 = LED_0: LED RED CLEAR 0402 SMD; Digikey Part Number: 67-1878-1-ND; MFG: LUMEX OPTO; Manuf Part Number: SML-LX0402SIC-TR; Manufacturer: LUMEX OPTO; Manufacturer Part Number: SML-LX0402SIC-TR; Part Number: SML-LX0402SIC-TR
FB1 = FERRITE: Ferrite; MFG: STEWARD; Part Number: HI0805R800R-10; RATING: 5A, 100MHz; SOURCE: DIGI 240-2395-1-ND
J17 = CON5: Connector, 5 pin; MFG: MOLEX; Part Number: 53398-0571; SOURCE: DIGI WM7609CT-ND
J22 = POWER_12V_INPUT_0: Connector, Power Jack; MFG: CUI; Part Number: PJ-002AH; SOURCE: DIGI CP-002AH-ND
J30 = CON3: Connector, 3 pin; MFG: MOLEX; Part Number: 53398-0371; SOURCE: DIGI WM7607CT-ND
J31 = HDR_0: Jumper, 1x2; MFG: HARWIN; Part Number: M22-2510205; SOURCE: DIGI 952-1311-ND
J32 = JUMPER_8A: Header, 8 pin; MFG: MOLEX; Part Number: 43045-0812; SOURCE: DIGI WM1792-ND
Q3 Q501-Q503 = 2N2222A: Transistor, NPN; MFG: FAIRCHILD; Part Number: MMBT2222A; RATING: 40V, 500mA; SOURCE: DIGI MMBT2222AFSCT-ND
Q4 = 2N2222A: Transistor, Darlington NPN; MFG: DIODES; Part Number: MMBT6427-7-F; RATING: 40V, 500mA; SOURCE: DIGI MMBT6427-FDICT-ND
Q5 = NTF6P02T3G_0: MOSFET, P-Channel; MFG: FAIRCHILD; SOURCE: DIGI NDT456PCT-ND
R8 R36 R48 R654 R656 R658 R691 R699 R700 = R: Resistor; ICA_MFR_NAME: PANASONIC; ICA_PARTNUM: $$1785048$$ERJ-3GSYJ102; MFG: PANASONIC; Part Number: ERJ-2GEJ332X; RATING: 1/10W; SOURCE: DIGI P3.3KJCT-ND; TOLERANCE: 5%
R45 R711 = R: Resistor; ICA_MFR_NAME: PANASONIC; ICA_PARTNUM: $$1785048$$ERJ-3GSYJ102; MFG: PANASONIC; Part Number: ERJ-2GEJ202X; RATING: 1/10W; SOURCE: DIGI P2.0KJCT-ND; TOLERANCE: 5%
R46 = R: Resistor; ICA_MFR_NAME: PANASONIC; ICA_PARTNUM: $$1785048$$ERJ-3GSYJ102; MFG: PANASONIC; Part Number: ERJ-2RKF4700X; RATING: 1/10W; SOURCE: DIGI P470LCT-ND; TOLERANCE: 1%
R47 = R: Resistor; ICA_MFR_NAME: PANASONIC; ICA_PARTNUM: $$1785048$$ERJ-3GSYJ102; MFG: PANASONIC; Part Number: ERJ-3GEYJ1R0V; RATING: 1/10W; SOURCE: DIGI P1.0GCT-ND; TOLERANCE: 5%
R60 = R: Resistor; ICA_MFR_NAME: PANASONIC; ICA_PARTNUM: $$1785048$$ERJ-3GSYJ102; MFG: PANASONIC; Part Number: ERJ-2RKF7680X; RATING: 1/10W; SOURCE: DIGI P768LCT-ND; TOLERANCE: 1%
R555 = R: Resistor; ICA_MFR_NAME: PANASONIC; ICA_PARTNUM: $$1785048$$ERJ-3GSYJ102; MFG: PANASONIC; Part Number: ERJ-2GEJ101X; RATING: 1/10W; SOURCE: DIGI P100JCT-ND; TOLERANCE: 5%
R556 = R: Resistor; ICA_MFR_NAME: PANASONIC; ICA_PARTNUM: $$1785048$$ERJ-3GSYJ102; MFG: PANASONIC; Part Number: ERJ-2GEJ105X; RATING: 1/10W; SOURCE: DIGI P1.0MJCT-ND; TOLERANCE: 5%
R557 R591 R615 R667 = R: Resistor; DNI: DNI; ICA_MFR_NAME: PANASONIC; ICA_PARTNUM: $$1785048$$ERJ-3GSYJ102; MFG: PANASONIC; Part Number: ERJ-2GE0R00X; RATING: 1/10W; SOURCE: DIGI P0.0JCT-ND
R22 R23 R550 R574 R575 R692 = R: Resistor; ICA_MFR_NAME: PANASONIC; ICA_PARTNUM: $$1785048$$ERJ-3GSYJ102; MFG: PANASONIC; Part Number: ERJ-2RKF1002X; RATING: 1/10W; SOURCE: DIGI P10.0KLCT-ND; TOLERANCE: 1%
R511 R587-R590 R592 R593 R607 R612-R614 R653 R655 R657 R666 = R: Resistor; ICA_MFR_NAME: PANASONIC; ICA_PARTNUM: $$1785048$$ERJ-3GSYJ102; MFG: PANASONIC; Part Number: ERJ-2GE0R00X; RATING: 1/10W; SOURCE: DIGI P0.0JCT-ND
R606 = R: Resistor; ICA_MFR_NAME: PANASONIC; ICA_PARTNUM: $$1785048$$ERJ-3GSYJ102; MFG: PANASONIC; Part Number: ERJ-2GEJ473X; RATING: 1/10W; SOURCE: DIGI P47KJCT-ND; TOLERANCE: 5%
R608 = R: Resistor; ICA_MFR_NAME: PANASONIC; ICA_PARTNUM: $$1785048$$ERJ-3GSYJ102; MFG: PANASONIC; Part Number: ERJ-2GEJ331X; RATING: 1/10W; SOURCE: DIGI P330JCT-ND; TOLERANCE: 5%
U17 = LM317L: IC, Voltage Regulator, Adjustable 1.2V-32V; MFG: TI; Part Number: LM317LIDR; SOURCE: DIGI 296-20680-1-ND
U505 = MSP430: IC, Microcontroller; MFG: TI; Part Number: MSP430F2011TPWR; SOURCE: DIGI 296-19689-1-ND
X500 = CRYSTAL: Crystal; MFG: DIODES Inc.; Part Number: GC2000032; SOURCE: DIGI GC2000032TR-ND; TOLERANCE: +/-25PPM
C27 = CAP_NP: Capacitor; MFG: TDK; Part Number: C2012X7R1E475K; RATING: 25V; SOURCE: DIGI 445-5972-1-ND; TOLERANCE: 10%; Type: X7R
C6 C28 C513 C608 = CAP_NP: Capacitor; MFG: KEMET; Part Number: C0805C224K5RACTU; RATING: 25V; SOURCE: DIGI 399-3491-1-ND; TOLERANCE: 10%; Type: X7R
C15 C31 C522 C524 C643 C647 = CAP_NP: Capacitor; MFG: SAMSUNG; Part Number: CL32A476KOJNNNE; RATING: 16V; SOURCE: DIGI 1276-3376-2-ND; TOLERANCE: 10%; Type: X5R
C22 C23 C552 C641 = CAP_NP: Capacitor; MFG: MURATA; Part Number: GRM32ER61C226KE20L; RATING: 16V; SOURCE: DIGI 490-1882-2-ND; TOLERANCE: 10%; Type: X5R
C505 C512 C518 C519 C607 C609 C632 C633 = CAP_NP: Capacitor; MFG: MURATA; Part Number: GRM21BR71E334KA01L; RATING: 25V; SOURCE: DIGI 490-1677-1-ND; TOLERANCE: 10%; Type: X7R
C610 C642 = CAP_NP: Capacitor; DNI: DNI; MFG: YAGEO; Part Number: CC0603JRNP09BN680; RATING: 50V; TOLERANCE: 5%; Type: NP0
C510 C634 = CAP_NP: Capacitor; DNI: DNI; MFG: YAGEO; Part Number: CC0603JRNP09BN181; RATING: 50V; TOLERANCE: 5%; Type: NP0
D1 D2 D4 D7 D8 = DIODE_SCHOTTKY: Diode, Schottky; MFG: DIODES INC; Part Number: B220A-13-F; RATING: 20V, 2A; SOURCE: DIGI B220A-FDICT-ND
D5 = DIODE: Diode; MFG: ON SEMI; Part Number: MURS320T3G; RATING: 200V, 4A; SOURCE: DIGI MURS320T3GOSCT-ND
D501 = DIODE_SCHOTTKY: Diode, Schottky; MFG: DIODES INC; Part Number: B340B-13-F; RATING: 40V, 3A; SOURCE: DIGIB340B-FDICT-ND
L5 = INDUCTOR: Inductor; ICA_MFR_NAME: STEWARD; ICA_PARTNUM: $$731362$$MI0603J680R-10; MFG: BOURNS; Part Number: SRR1005-150M; RATING: 1.7A; SOURCE: DIGI SRR1005-150M-ND; TOLERANCE: 20%
L1 L6 = INDUCTOR: Inductor; ICA_MFR_NAME: STEWARD; ICA_PARTNUM: $$731362$$MI0603J680R-10; MFG: BOURNS; Part Number: SRR1005-4R7M; RATING: 2.5A; SOURCE: DIGI SRR1005-4R7M-ND; TOLERANCE: 20%
L3 L8 L9 = INDUCTOR: Inductor; ICA_MFR_NAME: STEWARD; ICA_PARTNUM: $$731362$$MI0603J680R-10; MFG: BOURNS; Part Number: SRR1005-100M; RATING: 2A; SOURCE: DIGI SRR1005-100M-ND; TOLERANCE: 20%
Q2 = NTD14NO3RT4_1: MOSFET, N-Channel; MFG: ON SEMI; RATING: 25Vdss, 14A; SOURCE: DIGI NTD14N03RT4OSCT-ND
Q505 = NTD14NO3RT4_2: MOSFET, N-Channel; MFG: ON SEMI; RATING: 25Vdss, 14A; SOURCE: DIGI NTD14N03RT4OSCT-ND
R24 R26 R27 R35 R42 R43 R527 R551 R594 R702 = R: Resistor; ICA_MFR_NAME: PANASONIC; ICA_PARTNUM: $$1785048$$ERJ-3GSYJ102; MFG: VISHAY/DALE; Part Number: WSL0805R0100FEA; RATING: 1/8W; SOURCE: DIGI WSLA-.01CT-ND; TOLERANCE: 1%
R20 R41 R61 R698 = R: Resistor; DNI: DNI; ICA_MFR_NAME: PANASONIC; ICA_PARTNUM: $$1785048$$ERJ-3GSYJ102; MFG: VISHAY/DALE; Part Number: WSL0805R0100FEA; RATING: 1/8W; SOURCE: DIGI WSLA-.01CT-ND; TOLERANCE: 1%
R524 R526 R610 R659 = R: Resistor; ICA_MFR_NAME: PANASONIC; ICA_PARTNUM: $$1785048$$ERJ-3GSYJ102; MFG: PANASONIC; Part Number: ERA-2AEB202X; RATING: 1/16W; SOURCE: DIGI P2.0KDCCT-ND; TOLERANCE: 0.1%
R16 R611 = R: Resistor; ICA_MFR_NAME: PANASONIC; ICA_PARTNUM: $$1785048$$ERJ-3GSYJ102; MFG: PANASONIC; Part Number: ERJ-L06KF10CV; RATING: 1/8W; SOURCE: DIGI P100LLCT-ND; TOLERANCE: 1%
R616 R662 = R: Resistor; ICA_MFR_NAME: PANASONIC; ICA_PARTNUM: $$1785048$$ERJ-3GSYJ102; MFG: VISHAY; Part Number: CRCW040218K0FKED; RATING: 1/16W; SOURCE: DIGI 541-18.0KLCT-ND; TOLERANCE: 1%
R617 R663 = R: Resistor; ICA_MFR_NAME: PANASONIC; ICA_PARTNUM: $$1785048$$ERJ-3GSYJ102; MFG: VISHAY; Part Number: CRCW040214K3FKED; RATING: 1/16W; SOURCE: DIGI 541-14.3KLCT-ND; TOLERANCE: 1%
R523 R651 R652 = R: Resistor; ICA_MFR_NAME: PANASONIC; ICA_PARTNUM: $$1785048$$ERJ-3GSYJ102; MFG: PANASONIC; Part Number: ERA-2AEB162X; RATING: 1/16W; SOURCE: DIGI P1.6KDCCT-ND; TOLERANCE: 0.1%
R660 = R: Resistor; ICA_MFR_NAME: PANASONIC; ICA_PARTNUM: $$1785048$$ERJ-3GSYJ102; MFG: PANASONIC; Part Number: ERA-2AEB7870X; RATING: 1/16W; SOURCE: DIGI P787DCCT-ND; TOLERANCE: 0.1%
R661 = R: Resistor; ICA_MFR_NAME: PANASONIC; ICA_PARTNUM: $$1785048$$ERJ-3GSYJ102; MFG: PANASONIC; Part Number: ERA-2AEB182X; RATING: 1/16W; SOURCE: DIGI P2.0KDCCT-ND; TOLERANCE: 0.1%
R664 = R: Resistor; ICA_MFR_NAME: PANASONIC; ICA_PARTNUM: $$1785048$$ERJ-3GSYJ102; MFG: VISHAY; Part Number: CRCW04023K00FKED; RATING: 1/16W; SOURCE: DIGI 541-3.00KLCT-ND; TOLERANCE: 1%
R665 = R: Resistor; ICA_MFR_NAME: PANASONIC; ICA_PARTNUM: $$1785048$$ERJ-3GSYJ102; MFG: VISHAY; Part Number: CRCW040210K0FKED; RATING: 1/16W; SOURCE: DIGI 541-10.0KLCT-ND; TOLERANCE: 1%
U2 U15 = PMD1000_0: IC, Power and Motor Driver; MFG: TI; SOURCE: PROVIDED BY TI
U501 U507 U509 = AD525X: IC, Non-Volitile POT, 256 Positions; MFG: ANALOG DEVICES; Part Number: AD5252BRUZ100; RATING: 100K; SOURCE: DIGI AD5252BRUZ100-ND; TOLERANCE: 256 POS
C17 = CAP_NP: Capacitor; MFG: YAGEO; Part Number: CC0402JRNPO9BN220; RATING: 50V; SOURCE: DIGI 311-1018-2-ND; TOLERANCE: 5%; Type: NPO
C523 = CAP_NP: Capacitor; DNI: DNI; MFG: TDK; Part Number: C2012X7R1E475K; RATING: 25V; SOURCE: DIGI 445-5972-1-ND; TOLERANCE: 10%; Type: X7R
D500 = DIODE: Diode; MFG: ON SEMI; RATING: 200V; SOURCE: DIGI MURS220T3GOSCT-ND
L4 = INDUCTOR: Inductor; MFG: WURTH; Part Number: 7447789002; RATING: 4.02 A; SOURCE: DIGI 732-1173-2-ND; TOLERANCE: 20%
Q1 = NTD14NO3RT4_3: MOSFET, N-Channel; MFG: ON SEMI; RATING: 25Vdss, 14A; SOURCE: DIGI NTD14N03RT4OSCT-ND
Q500 = NTD14NO3RT4_4: MOSFET, N-Channel; MFG: ON SEMI; RATING: 25Vdss, 14A; SOURCE: DIGI NTD14N03RT4OSCT-ND
R17 = R: Resistor; MFG: PANASONIC; Part Number: ERJ-2RKF1693X; RATING: 1/10W; SOURCE: DIGI P169KLTR-ND; TOLERANCE: 1%
R21 = R: Resistor; MFG: PANASONIC; Part Number: ERJ-2RKF1103X; RATING: 1/10W; SOURCE: DIGI P110KLCT-ND; TOLERANCE: 1%
R509 = R: Resistor; ICA_MFR_NAME: PANASONIC; ICA_PARTNUM: $$1785048$$ERJ-3GSYJ102; MFG: VISHAY/DALE; Part Number: CRCW0402909RFKED; RATING: 1/16W; SOURCE: DIGI 541909LCT-ND; TOLERANCE: 1%
R510 = R: Resistor; ICA_MFR_NAME: PANASONIC; ICA_PARTNUM: $$1785048$$ERJ-3GSYJ102; MFG: YAGEO; Part Number: RC0402FR-075K1L; RATING: 1/16W; SOURCE: DIGI 311-5.1KLRCT-ND; TOLERANCE: 1%
R516 = R: Resistor; MFG: PANASONIC; Part Number: ERJ-2RKF2492X; RATING: 1/10W; SOURCE: DIGI P24.9KLCT-ND; TOLERANCE: 1%
R521 = R: Resistor; MFG: PANASONIC; Part Number: ERJ-2RKF8062X; RATING: 1/10W; SOURCE: DIGI P80.6KLTR-ND; TOLERANCE: 1%
R525 = R: Resistor; ICA_MFR_NAME: PANASONIC; ICA_PARTNUM: $$1785048$$ERJ-3GSYJ102; MFG: PANASONIC; Part Number: ERA-2AEB102X; RATING: 1/16W; SOURCE: DIGI P1.0KDCCT-ND; TOLERANCE: 0.1%
U7 = TPS54327: IC, Switching Voltage Regulator; MFG: TI; Part Number: TPS54327DDA
U11 = DDP442x: IC, ASIC; MFG: TI; SOURCE: PROVIDED BY TI

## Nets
GND: C15.1 C16.1 C18.1 C19.2 C20.2 C22.1 C23.1 C27.1 C31.1 C32.1 C33.1 C34.1 C35.1 C37.1 C39.1 C40.1 C512.1 C513.2 C518.1 C519.1 C522.1 C523.2 C524.1 C525.1 C531.2 C532.2 C547.2 C548.1 C552.1 C574.1 C578.2 C605.1 C606.2 C607.1 C608.2 C611.1 C613.2 C614.2 C615.2 C616.2 C617.2 C618.2 C619.2 C620.2 C621.2 C622.2 C631.2 C632.1 C633.1 C639.2 C641.1 C643.1 C647.1 D1.2(A) D2.2(A) D4.2(A) D7.2(A) D8.2(A) D9.2(CATHODE) D10.2(CATHODE) D501.2(A) J17.5 J22.GND1(2) J22.GND2(3) J30.3 J32.1 J32.3 J32.5 J32.7 J45.2 Q3.1(EMITTER) Q4.1(EMITTER) Q501.1(EMITTER) Q502.1(EMITTER) Q503.1(EMITTER) R44.2 R60.2 R510.1 R516.2 R521.2 R523.1 R526.1 R617.1 R651.2 R652.1 R661.1 R663.1 R665.1 TP36.1 U2.7(GND) U2.19(GND) U2.44(GND) U7.5(GND) U7.9(GND_PAD) U15.7(GND) U15.19(GND) U15.44(GND) U501.8(GND) U501.10(DGND) U505.14(VSS) U507.8(GND) U507.10(DGND) U507.11(AD1) U509.2(AD0) U509.8(GND) U509.10(DGND) ; also on sheet 1 4 5 6 7 8 9 10 11 12 13 14 20 21
P5V: R27.1 R698.2 TP25.1 ; also on sheet 5 7 12 13 20 21
P5V_CONN: J32.4 R698.1
P12V: C19.1 C20.1 C505.2 C512.2 C518.2 C519.2 C606.1 C607.2 C609.2 C631.1 C632.2 C633.2 C639.1 J31.2 Q5.2(D2) Q5.4(D4) R16.2 R22.2 R550.1 R611.2 R691.1 R700.1 R701.1 TP43.1 U2.22(VBB1) U2.23(LX5) U2.27(ISENK) U2.37(VBB2) U2.42(VBB4) U2.43(LX33) U7.8(VIN) U15.22(VBB1) U15.27(ISENK) U15.37(VBB2) U15.42(VBB4) ; also on sheet 1 6 13 14 21
P12V_FIL: C33.2 C36.1 FB1.2 J31.1 Q5.3(S) R45.2 R47.1 R48.1 TP45.1
P12V_IN: C32.2 FB1.1 J22.P12V_IN(1) J32.6
A1P8V: R594.1 ; also on sheet 4
A1P8V_SENSE: C27.2 C610.2 R594.2 R610.1 R616.2 TP32.1 U15.29(VLIN1)
AFE_CLK: R579.2 U11.AD12(AFE_CLK)
AFE_RSTZ: U11.AC12(AFE_ARSTZ) ; also on sheet 20 21
ALF_CSYNC: TP2.1 U11.AE11(ALF_CSYNC) ; also on sheet 21
ALF_HSYNC: TP24.1 U11.AD11(ALF_HSYNC) ; also on sheet 21
ALF_VSYNC: TP1.1 U11.AF11(ALF_VSYNC) ; also on sheet 21
BT656_B_D6: R557.1 ; also on sheet 20
CSZ5_DAD2: R65.1 ; also on sheet 1
CW_INDEX1: U11.AF7(CW_INDEX) ; also on sheet 13 20
CW_PWM1: U11.AD8(CW_PWM) ; also on sheet 14
DA0: C615.1 R628.1 U11.AB8(DADADDR_0)
DA1: C616.1 R629.1 U11.AF4(DADADDR_1)
DA2: C618.1 R673.1 U11.AE5(DADADDR_2)
DA3: C621.1 R635.1 U11.AD6(DADADDR_3)
DADADD0: R628.2 ; also on sheet 1
DADADD1: R629.2 ; also on sheet 1
DADADD2: R673.2 ; also on sheet 1
DADADD3: R635.2 ; also on sheet 1
DADINTZ: R595.2 R713.2 ; also on sheet 1
DADMD0: R634.2 ; also on sheet 1
DADMD1: R627.2 ; also on sheet 1
DADOEZ: R633.2 R714.2 ; also on sheet 1
DADSEL0: R626.2 ; also on sheet 1
DADSEL1: R630.2 ; also on sheet 1
DADSTB: R636.2 TP47.1 ; also on sheet 1
DINTZ: C578.1 R595.1 U11.AC8(DAD_INTZ)
DM0: C620.1 R634.1 U11.AE6(DADMODE_0)
DM1: C614.1 R627.1 U11.AD7(DADMODE_1)
DMD_P3P3V: C35.2 C39.2 FB2.1 FB3.1 J46.2 R66.1 R712.1 R713.1 R714.1
DMDP3P3VA: C40.2 FB3.2 ; also on sheet 1
DMDP3P3VB: C34.2 FB2.2 ; also on sheet 1
DMDSPARE0: R44.1 ; also on sheet 1
DOEZ: C619.1 R633.1 U11.AE7(DADOEZ)
DS0: C613.1 R626.1 U11.AC7(DADSEL_0)
DS1: C617.1 R630.1 U11.AE4(DADSEL_1)
DSP_P1P8V: J12.2 ; also on sheet 20 21
DSTB: C622.1 R636.1 U11.AF5(DADSTRB)
EXT_ARSTZ: R8.2 TP4.1 U11.T24(EXT_RSTZ) ; also on sheet 1 13 20
EXT_CLK: R579.1 ; also on sheet 21
FAN1_SW: U15.40(F1SW) ; also on sheet 13
FAN2_SW: U15.39(F2SW) ; also on sheet 13
FAN3_SW: U15.38(F3SW) ; also on sheet 13
FAN4_SW: U2.40(F1SW) ; also on sheet 13
FAN5_SW: J3.1 U2.39(F2SW) ; also on sheet 13
FAN6_SW: J3.3 ; also on sheet 13
FAN6_SW_JUMP: J3.2 U2.38(F3SW)
FE_P1P2V: J13.2 ; also on sheet 20 21
FIELD: U11.AF9(GPIO_78) ; also on sheet 12 21
HDMI_CEC: TP5.1 U11.G23(GPIO_55) ; also on sheet 21
HDMI_INT: TP18.1 U11.AB13(AFE_IRQ) ; also on sheet 21
KEYPD_PWR: R588.1 ; also on sheet 11
LP_DRIVE: R574.1 R575.1 U505.5(P1.3)
LP_IR0: R590.1 ; also on sheet 11
LP_IR1: R593.1 ; also on sheet 11
LP_P1_0: R588.2 U505.2(P1.0)
LP_P1_5: R590.2 U505.7(P1.5)
LP_P1_6: R593.2 U505.8(P1.6)
LP_P2_6: R591.2 U505.13(P2.6)
LP_P2_7: R592.2 U505.12(P2.7)
LP_TA0: R589.2 U505.3(TA0)
LP_TCK: J17.2 R608.1
LP_TDO_TDI: C605.2 J17.4 R606.1 U505.10(SBWTDIO)
LP_TEST_VPP: J17.3 R608.2 U505.11(SBWTCK)
M_DCLKA_N: U11.V3(DCKA_N) ; also on sheet 1
M_DCLKA_P: U11.V4(DCKA_P) ; also on sheet 1
M_DCLKB_N: U11.J4(DCKB_N) ; also on sheet 1
M_DCLKB_P: U11.J3(DCKB_P) ; also on sheet 1
M_DDA00_N: U11.P3(DDA_N_15) ; also on sheet 1
M_DDA00_P: U11.P4(DDA_P_15) ; also on sheet 1
M_DDA01_N: U11.P1(DDA_N_14) ; also on sheet 1
M_DDA01_P: U11.P2(DDA_P_14) ; also on sheet 1
M_DDA02_N: U11.R3(DDA_N_13) ; also on sheet 1
M_DDA02_P: U11.R4(DDA_P_13) ; also on sheet 1
M_DDA03_N: U11.R1(DDA_N_12) ; also on sheet 1
M_DDA03_P: U11.R2(DDA_P_12) ; also on sheet 1
M_DDA04_N: U11.T3(DDA_N_11) ; also on sheet 1
M_DDA04_P: U11.T4(DDA_P_11) ; also on sheet 1
M_DDA05_N: U11.T1(DDA_N_10) ; also on sheet 1
M_DDA05_P: U11.T2(DDA_P_10) ; also on sheet 1
M_DDA06_N: U11.U3(DDA_N_9) ; also on sheet 1
M_DDA06_P: U11.U4(DDA_P_9) ; also on sheet 1
M_DDA07_N: U11.U1(DDA_N_8) ; also on sheet 1
M_DDA07_P: U11.U2(DDA_P_8) ; also on sheet 1
M_DDA08_N: U11.W3(DDA_N_7) ; also on sheet 1
M_DDA08_P: U11.W4(DDA_P_7) ; also on sheet 1
M_DDA09_N: U11.W1(DDA_N_6) ; also on sheet 1
M_DDA09_P: U11.W2(DDA_P_6) ; also on sheet 1
M_DDA10_N: U11.Y1(DDA_N_5) ; also on sheet 1
M_DDA10_P: U11.Y2(DDA_P_5) ; also on sheet 1
M_DDA11_N: U11.Y3(DDA_N_4) ; also on sheet 1
M_DDA11_P: U11.Y4(DDA_P_4) ; also on sheet 1
M_DDA12_N: U11.AA1(DDA_N_3) ; also on sheet 1
M_DDA12_P: U11.AA2(DDA_P_3) ; also on sheet 1
M_DDA13_N: U11.AA3(DDA_N_2) ; also on sheet 1
M_DDA13_P: U11.AA4(DDA_P_2) ; also on sheet 1
M_DDA14_N: U11.AB1(DDA_N_1) ; also on sheet 1
M_DDA14_P: U11.AB2(DDA_P_1) ; also on sheet 1
M_DDA15_N: U11.AC1(DDA_N_0) ; also on sheet 1
M_DDA15_P: U11.AC2(DDA_P_0) ; also on sheet 1
M_DDB00_N: U11.N2(DDB_N_15) ; also on sheet 1
M_DDB00_P: U11.N1(DDB_P_15) ; also on sheet 1
M_DDB01_N: U11.N4(DDB_N_14) ; also on sheet 1
M_DDB01_P: U11.N3(DDB_P_14) ; also on sheet 1
M_DDB02_N: U11.M1(DDB_N_13) ; also on sheet 1
M_DDB02_P: U11.M2(DDB_P_13) ; also on sheet 1
M_DDB03_N: U11.M4(DDB_N_12) ; also on sheet 1
M_DDB03_P: U11.M3(DDB_P_12) ; also on sheet 1
M_DDB04_N: U11.L2(DDB_N_11) ; also on sheet 1
M_DDB04_P: U11.L1(DDB_P_11) ; also on sheet 1
M_DDB05_N: U11.L4(DDB_N_10) ; also on sheet 1
M_DDB05_P: U11.L3(DDB_P_10) ; also on sheet 1
M_DDB06_N: U11.K2(DDB_N_9) ; also on sheet 1
M_DDB06_P: U11.K1(DDB_P_9) ; also on sheet 1
M_DDB07_N: U11.K4(DDB_N_8) ; also on sheet 1
M_DDB07_P: U11.K3(DDB_P_8) ; also on sheet 1
M_DDB08_N: U11.H2(DDB_N_7) ; also on sheet 1
M_DDB08_P: U11.H1(DDB_P_7) ; also on sheet 1
M_DDB09_N: U11.H4(DDB_N_6) ; also on sheet 1
M_DDB09_P: U11.H3(DDB_P_6) ; also on sheet 1
M_DDB10_N: U11.G2(DDB_N_5) ; also on sheet 1
M_DDB10_P: U11.G1(DDB_P_5) ; also on sheet 1
M_DDB11_N: U11.G4(DDB_N_4) ; also on sheet 1
M_DDB11_P: U11.G3(DDB_P_4) ; also on sheet 1
M_DDB12_N: U11.F2(DDB_N_3) ; also on sheet 1
M_DDB12_P: U11.F1(DDB_P_3) ; also on sheet 1
M_DDB13_N: U11.F4(DDB_N_2) ; also on sheet 1
M_DDB13_P: U11.F3(DDB_P_2) ; also on sheet 1
M_DDB14_N: U11.E2(DDB_N_1) ; also on sheet 1
M_DDB14_P: U11.E1(DDB_P_1) ; also on sheet 1
M_DDB15_N: U11.D2(DDB_N_0) ; also on sheet 1
M_DDB15_P: U11.D1(DDB_P_0) ; also on sheet 1
M_SCTRLA_N: U11.V1(SCA_N) ; also on sheet 1
M_SCTRLA_P: U11.V2(SCA_P) ; also on sheet 1
M_SCTRLB_N: U11.J2(SCB_N) ; also on sheet 1
M_SCTRLB_P: U11.J1(SCB_P) ; also on sheet 1
MC_VCC: C547.1 C574.2 R587.2 R606.2 U505.1(VCC)
MODEB: J45.1 R66.2 ; also on sheet 1
MTR_ARSTZ: R36.2 TP15.1 U2.48(RESETZ) U11.T25(MTR_ARSTZ) U15.48(RESETZ)
OCLKA: R578.1 ; also on sheet 14
OCLKA_RES: R578.2 U11.AF6(OCLKA)
P1_A0: U11.AE12(P1_A0) ; also on sheet 21
P1_A1: U11.AF12(P1_A1) ; also on sheet 21
P1_A2: U11.AF13(P1_A2) ; also on sheet 21
P1_A3: U11.AF14(P1_A3) ; also on sheet 21
P1_A4: U11.AC13(P1_A4) ; also on sheet 21
P1_A5: U11.AD13(P1_A5) ; also on sheet 21
P1_A6: U11.AE13(P1_A6) ; also on sheet 21
P1_A7: U11.AE14(P1_A7) ; also on sheet 21
P1_A8: U11.AE15(P1_A8) ; also on sheet 21
P1_A9: U11.AD15(P1_A9) ; also on sheet 21
P1_B0: U11.AD14(P1_B0) ; also on sheet 21
P1_B1: U11.AC14(P1_B1) ; also on sheet 21
P1_B2: U11.AF15(P1_B2) ; also on sheet 21
P1_B3: U11.AF16(P1_B3) ; also on sheet 21
P1_B4: U11.AE16(P1_B4) ; also on sheet 21
P1_B5: U11.AD16(P1_B5) ; also on sheet 21
P1_B6: U11.AC16(P1_B6) ; also on sheet 21
P1_B7: U11.AC15(P1_B7) ; also on sheet 21
P1_B8: U11.AB18(P1_B8) ; also on sheet 21
P1_B9: U11.AF18(P1_B9) ; also on sheet 21
P1_C0: U11.AE18(P1_C0) ; also on sheet 21
P1_C1: U11.AC19(P1_C1) ; also on sheet 21
P1_C2: U11.AF20(P1_C2) ; also on sheet 21
P1_C3: U11.AF19(P1_C3) ; also on sheet 21
P1_C4: U11.AE19(P1_C4) ; also on sheet 21
P1_C5: U11.AD19(P1_C5) ; also on sheet 21
P1_C6: U11.AF21(P1_C6) ; also on sheet 21
P1_C7: U11.AE21(P1_C7) ; also on sheet 21
P1_C8: U11.AE20(P1_C8) ; also on sheet 21
P1_C9: U11.AD20(P1_C9) ; also on sheet 21
P1_HSYNC: TP10.1 U11.AD21(P1_HSYNC) ; also on sheet 21
P1_VSYNC: TP12.1 U11.AC20(P1_VSYNC) ; also on sheet 21
P1P1V: C31.2 C634.2 J13.1 R35.2 R660.2 R664.2 TP35.1 ; also on sheet 4
P1P2V_PMD2: C15.2 C510.2 J13.3 R509.2 R525.2 R527.2 TP14.1
P1P8V: J12.1 R702.1 TP40.1 ; also on sheet 4
P1P8V_PMD2: J12.3 R551.1 TP17.1
P2_A0: U11.AB19(P2_A0) ; also on sheet 21
P2_A1: U11.AE23(P2_A1) ; also on sheet 21
P2_A2: U11.AD22(P2_A2) ; also on sheet 21
P2_A3: U11.AC21(P2_A3) ; also on sheet 21
P2_A4: U11.AB20(P2_A4) ; also on sheet 21
P2_A5: U11.AD23(P2_A5) ; also on sheet 21
P2_A6: U11.AC22(P2_A6) ; also on sheet 21
P2_A7: U11.AB21(P2_A7) ; also on sheet 21
P2_A8: U11.AD25(P2_A8) ; also on sheet 21
P2_A9: U11.AD26(P2_A9) ; also on sheet 21
P2_B0: U11.AC24(P2_B0) ; also on sheet 21
P2_B1: U11.AC25(P2_B1) ; also on sheet 21
P2_B2: U11.AB23(P2_B2) ; also on sheet 21
P2_B3: U11.AC26(P2_B3) ; also on sheet 21
P2_B4: U11.AB24(P2_B4) ; also on sheet 21
P2_B5: U11.AA22(P2_B5) ; also on sheet 21
P2_B6: U11.AB25(P2_B6) ; also on sheet 21
P2_B7: U11.AA23(P2_B7) ; also on sheet 21
P2_B8: U11.AB26(P2_B8) ; also on sheet 21
P2_B9: U11.Y22(P2_B9) ; also on sheet 21
P2_C0: U11.AA24(P2_C0) ; also on sheet 21
P2_C1: U11.AA25(P2_C1) ; also on sheet 21
P2_C2: U11.AA26(P2_C2) ; also on sheet 21
P2_C3: U11.W22(P2_C3) ; also on sheet 21
P2_C4: U11.Y23(P2_C4) ; also on sheet 21
P2_C5: U11.Y24(P2_C5) ; also on sheet 21
P2_C6: U11.Y25(P2_C6) ; also on sheet 21
P2_C7: U11.Y26(P2_C7) ; also on sheet 21
P2_C8: U11.V22(P2_C8) ; also on sheet 21
P2_C9: U11.W23(P2_C9) ; also on sheet 21
P2_HSYNC: TP7.1 U11.W26(P2_HSYNC) ; also on sheet 21
P2_VSYNC: TP19.1 U11.U22(P2_VSYNC) ; also on sheet 21
P2P5V: Q505.2(D2) Q505.4(D4) R41.1 R43.2 TP39.1 ; also on sheet 20 21
P2P5V_CONN: J32.8 R20.2 R41.2
P2P5V_PMD2: Q500.2(D2) Q500.4(D4) R20.1 R24.2 TP16.1
P3P3V: J46.1 R8.1 R23.2 R36.1 R42.2 R61.1 R654.1 R656.1 R658.1 TP42.1 ; also on sheet 4 5 6 7 8 9 10 11 12 13 14 20 21
P3P3V_CONN: J32.2 R61.2 R615.2 R667.2
P3P3V_EX: J46.3 R26.2 TP23.1
P3P3V_LP: C37.2 C548.2 C611.2 R46.1 R511.2 R575.2 R587.1 R607.1 R614.2 R666.2 TP20.1 U17.2(OUT1) U17.3(OUT2) U17.6(OUT3) U17.7(OUT4) ; also on sheet 9 11
P_CLK1: TP6.1 U11.AE22(P_CLK1) ; also on sheet 21
P_CLK2: TP8.1 U11.W25(P_CLK2) ; also on sheet 21
P_CLK3: TP11.1 U11.AF23(P_CLK3) ; also on sheet 21
P_DATAEN1: TP13.1 U11.AF22(P_DATAEN1) ; also on sheet 21
P_DATAEN2: TP9.1 U11.W24(P_DATAEN2) ; also on sheet 21
P_INTZ: R657.1 U2.36(PMDINTZ)
PGOOD: R655.1 U2.35(PWRGOOD)
PMD1K2_CP1: C6.1 U2.18(CP1)
PMD1K2_CP2: C6.2 U2.17(CP2)
PMD1K2_FB_P2P5V: C524.2 L3.2 R24.1 U2.46(V2P5)
PMD1K2_GD_CORE: Q1.1(G) U2.26(GDC)
PMD1K2_VCP: C505.1 U2.21(VCP)
PMD1K2_VREG: C513.1 U2.20(VREG) U2.24(V5) U2.31(FB1) U2.45(V3P3) U2.47(TRIM)
PMD1K_CP1: C28.1 U15.18(CP1)
PMD1K_CP2: C28.2 U15.17(CP2)
PMD1K_FB_LIN1: C610.1 R610.2 R651.1 U15.31(FB1) U507.4(W1)
PMD1K_FB_P2P5V: C647.2 L9.2 R43.1 U15.46(V2P5)
PMD1K_FB_P3P3V: C641.2 L8.2 R42.1 U15.45(V3P3)
PMD1K_FB_P5V: C552.2 L5.1 R27.2 U15.24(V5)
PMD1K_GD_CORE: Q2.1(G) U15.26(GDC)
PMD1K_VCP: C609.1 U15.21(VCP)
PMD1K_VREG: C608.1 U15.20(VREG) U15.47(TRIM)
PMD_INTZ: R657.2 R658.2 R692.1 U11.AE8(PMD_INTZ) U15.36(PMDINTZ)
POSENSE: R554.1 R653.2 R654.2 U15.34(POSENSE) ; also on sheet 8
POSENSE_FIL: C525.2 R554.2 U11.P22(POSENSE)
PSENS: R653.1 U2.34(POSENSE)
PWR_OFF_RDY: U11.B23(GPIO_16) U505.9(P1.7)
PWR_ON_AC: J30.1 R592.1
PWR_ON_RDY: U11.C22(GPIO_17) U505.6(P1.4)
PWRGOOD: R655.2 R656.2 U11.T26(PWRGOOD) U15.35(PWRGOOD) ; also on sheet 8 9 10 11 12
SCL0: R612.2 ; also on sheet 11 12 20
SCL_VMON: R612.1 U501.9(SCL) U507.9(SCL) U509.9(SCL)
SDA0: R613.2 ; also on sheet 11 12 20
SDA_VMON: R613.1 U501.7(SDA) U507.7(SDA) U509.7(SDA)
SSP0_CLK: U2.2(CLK) U15.2(CLK) ; also on sheet 9
SSP0_CSZ2_PMD1: U15.4(CSZ) ; also on sheet 9
SSP0_CSZ3_PMD2: U2.4(CSZ) ; also on sheet 9
SSP0_CSZ5/SPD6: R65.2 ; also on sheet 12 13
SSP0_RXD: R648.2 R650.2 R712.2 ; also on sheet 1 9
SSP0_TXD: U2.3(DIN) U15.3(DIN) ; also on sheet 9
SW_EN: Q501.3(COLLECTOR) R550.2 U7.1(EN)
SW_SS: C18.2 U7.4(SS)
SWNODE2_CORE: D1.1(C) L1.1 Q1.3(S) U2.25(LXC)
SWNODE2_P2P5V: D2.1(C) L3.1 U2.41(LX25)
SWNODE_CORE: D501.1(C) L6.1 Q2.3(S) U15.25(LXC)
SWNODE_P2P5V: D7.1(C) L9.1 U15.41(LX25)
SWNODE_P3P3V: D8.1(C) L8.1 U15.43(LX33)
SWNODE_P5V: D4.1(C) L5.2 U15.23(LX5)
UART0_RTSZ_BUF: R591.1 ; also on sheet 9
UART0_RXD: R589.1 ; also on sheet 9
XTAL_IN: C532.1 R556.1 R557.2 U11.M26(MOSCP) X500.1
XTAL_OUT: R555.2 R556.2 U11.N26(MOSCN)
N16804199: D11.2(CATHODE) R699.1
N16826457: Q4.3(COLLECTOR) R699.2
N16826574: Q3.3(COLLECTOR) Q4.2(BASE) R691.2
N16826732: Q503.3(COLLECTOR) R711.1
N16826745: Q3.2(BASE) R692.2
N16826772: J17.1 R607.2
N16826808: C36.2 Q5.1(G) R45.1 R711.2
N16827011: C531.1 R555.1 X500.2
N16827097: Q503.2(BASE) R574.2
N16827292: R650.1 U15.1(DOUT)
N16827323: R46.2 R60.1 U17.4(ADJ)
N16827429: D9.1(ANODE) R700.2
N16827460: R47.2 U17.1(IN)
N16827499: D11.1(ANODE) R701.2
N16827743: D10.1(ANODE) R48.2
N16830133: R666.1 R667.1 U509.1(VDD) U509.3(WPZ) U509.11(AD1)
N16830205: C634.1 R660.1 R661.2 U15.30(/FBC) U509.4(W1)
N16830232: Q2.2(D2) Q2.4(D4) R611.1 U15.28(ISEN)
N16830236: D5.2(A) L6.2
N16830344: C642.2 C643.2 Q505.3(S) R659.2 R662.2 R702.2
N16830356: R616.1 U507.6(A1)
N16830372: D5.1(K) R35.1
N16830397: R617.2 U507.5(B1)
N16830529: R614.1 R615.1 U507.1(VDD) U507.2(AD0) U507.3(WPZ)
N16830564: R664.1 U509.6(A1)
N16830576: C642.1 R652.2 R659.1 U15.32(FB2) U509.14(W3)
N16830606: Q505.1(G) U15.33(GD2)
N16830689: R662.1 U509.12(A3)
N16830707: R663.2 U509.13(B3)
N16830891: R665.2 U509.5(B1)
N16985744: R648.1 U2.1(DOUT)
N17060093: R511.1 U501.1(VDD) U501.2(AD0) U501.3(WPZ) U501.11(AD1)
N17060097: C510.1 R525.1 R526.2 U2.30(/FBC) U501.4(W1)
N17060101: Q1.2(D2) Q1.4(D4) R16.1 U2.28(ISEN)
N17060103: D500.2(A) L1.2
N17060105: D500.1(K) R527.1
N17060121: R510.2 U501.5(B1)
N17060167: R509.1 U501.6(A1)
N17350387: R523.2 R524.1 U2.32(FB2)
N17350626: C522.2 Q500.3(S) R524.2 R551.2
N17413439: Q500.1(G) U2.33(GD2)
N18269038: C16.2 U7.3(VREG5)
N18269088: C17.1 R21.2 R516.1 U7.2(VFB) U501.14(W3)
N18269114: R521.1 U501.12(A3)
N18269160: C17.2 C22.2 C23.2 L4.2 R17.1 R21.1 R26.1
N18269218: R17.2 U501.13(B3)
N18269262: C523.1 Q502.2(BASE) R23.1
N18269320: Q501.2(BASE) Q502.3(COLLECTOR) R22.1
N18269375: C21.1 L4.1 U7.6(SW)
N18374429: C21.2 U7.7(VBST)

Not connected (* = marked no-connect by the designer): J30 2*; U2 29(VLIN1)*; U17 5(NC)* 8(NC)*; U505 4(TA1)*; U507 12(A3)* 13(B3)* 14(W3)*

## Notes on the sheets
sheet 15
- 4
- NOTE:
  Consult the DLPA100 Data Sheet for
  external component specifications.
- DPAK
- IMPORTANT NOTE:
  The PCB should be designed such that the
  specifications are not exceeded when the
  DLPC4430 is operated under the maximum current
  conditions specified in the DLPC4430 datasheet.
- NOTE:
  R20, R24, R26, R527, R551 are used
  for current measurement and are not required for
  production units.
- 2
- 1
- 3
- These components are for characterization only.
  They are not required for production designs.
- 4
- DPAK
- 2
- 1
- 3
- Note:
  Jumper Pin 1 to Pin 2 for PMD1
  Jumper Pin 2 to Pin 3 for PMD2
  Important: When using Advanced Connectivity Daughter
  Card, jumper configuration must match
- Note:
  Jumper Pin 1 to Pin 2 for High Current Fan 5 (Fan 6 Disabled)
  Jumper Pin 2 to Pin 3 for Fan 5 and Fan 6 normal current
  Default: Pin 2 to Pin 3
- Secondary DLPA100 Supplies
- (C) COPYRIGHT 2023
         Texas Instruments
        All Rights Reserved
sheet 16
- NOTE:
  R27, R35, R42, R43, R594, R702 are used
  for current measurement and are not required for
  production units.
  R61, R41, R698, R615 are used for alternate
  lab supplies and are not required for production units.
- 4
- NOTE:
  Consult the DLPA100 Data Sheet for
  external component specifications.
- DPAK
- IMPORTANT NOTE:
  The PCB should be designed such that the
  specifications are not exceeded when the
  DLPC4430 is operated under the maximum current
  conditions specified in the DLPC4430 datasheet.
- 2
- 1
- 3
- These components are
  for characterization only.
  They are not required for
  production designs.
- Note: VDD Spec was changed
  for DLPC4430.  R660 and
  R661 reflect the new VDD
  spec of 1.15V. For
  DLPC4420, the VDD spec did
  not change, R660 should be
  750 ohms, and R661 should
  be 2 kohms.
- These components are for characterization only.
  They are not required for production designs.
- 4
- DPAK
- 2
- 1
- 3
- These components are
  for characterization only.
  They are not required for
  production designs.
- Primary DLPA100 Power Supplies
- (C) COPYRIGHT 2023
         Texas Instruments
        All Rights Reserved
sheet 17
- NOTE:
  Install jumper for normal power mode. (DEFAULT)
  Un-install jumper for ultra-low power mode.
- 4
- SOT-223
- 1
- 2
- 3
- These components are installed
  for ultra-low power mode.
- NOTE:
  Place regulator near 12V input
  power filtering. Otherwise, install
  0.1uF bypass capacitor on input.
- (DUAL_CLKIN)
- AC BALLAST
  SHUTDOWN
- Input Power and DLPA100/ DLPC4430 Interface
- (C) COPYRIGHT 2023
         Texas Instruments
        All Rights Reserved
sheet 18
- Note:
  Jumper Pin 1 to Pin 2 for Low Current DMDs
  Jumper Pin 2 to Pin 3 for High Current DMDs
  Default: Pin 1 to Pin 2
  PMD typical output current on P3P3V is 1.6 A
- J45 not installed - Half Bus Mode
  J45 installed - Full Bus Mode
- Note: Filtering required for TI
  Reference Design only for
  Impedance Mismatch with Flex Cable
- DMD Interface
- (C) COPYRIGHT 2023
         Texas Instruments
        All Rights Reserved
sheet 19
- Front End Interface
- (C) COPYRIGHT 2023
         Texas Instruments
        All Rights Reserved
